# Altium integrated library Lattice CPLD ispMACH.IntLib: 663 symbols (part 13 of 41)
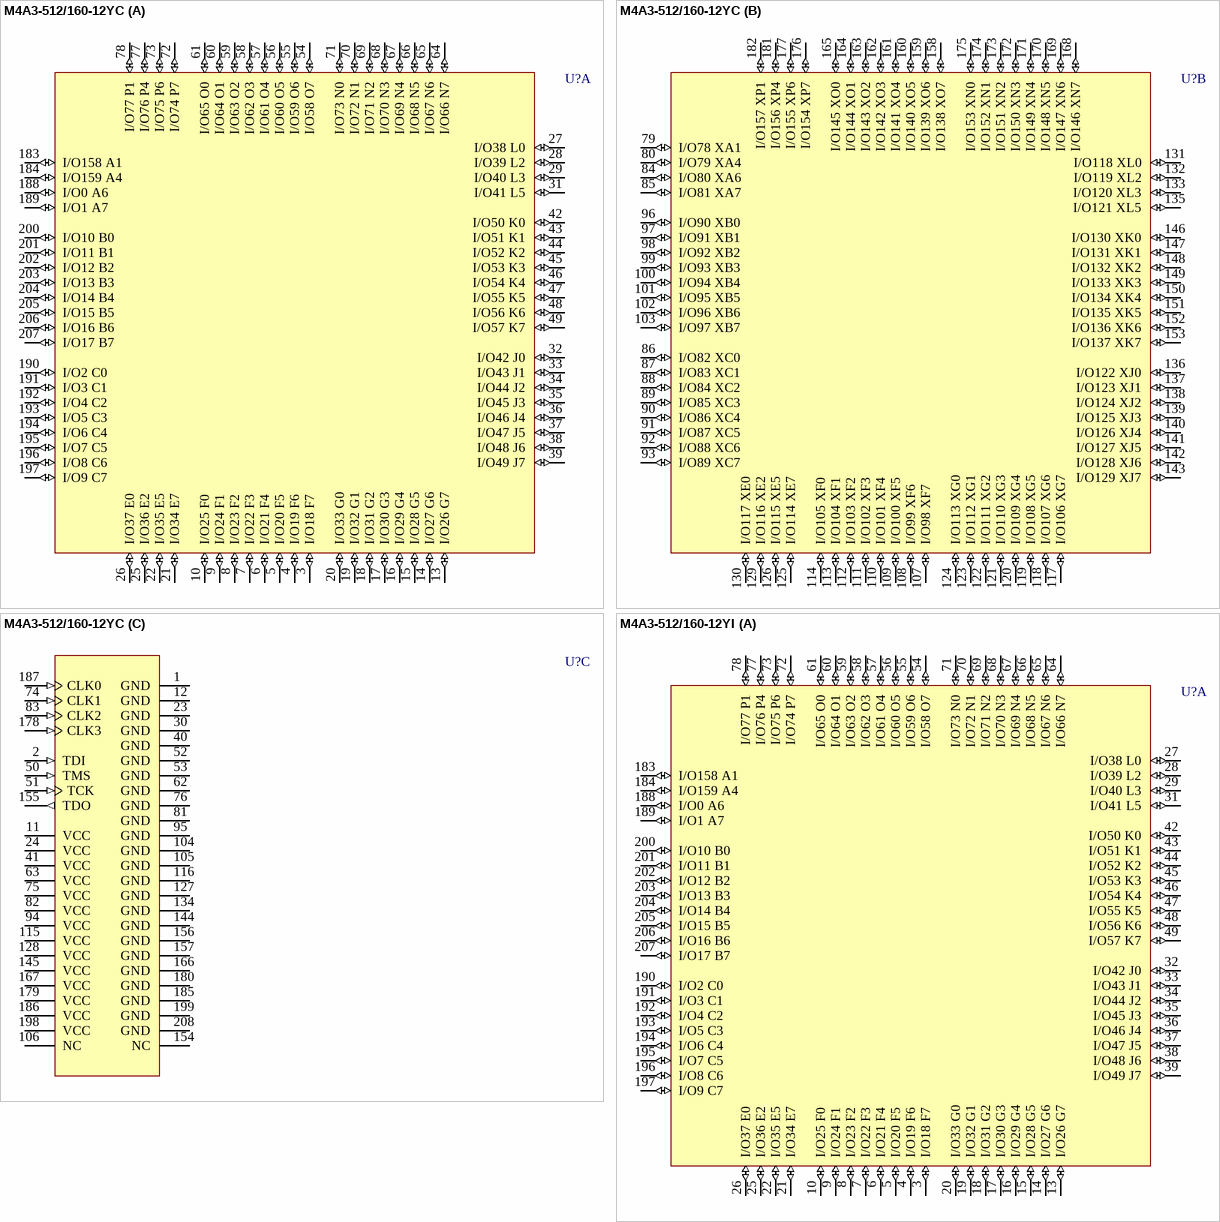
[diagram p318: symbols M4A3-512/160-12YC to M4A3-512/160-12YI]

## M4A3-512/160-12YC
designator U?
High-Performance EE CMOS In-System Programmable Logic
footprint PQFP208_N (Shrink QFP, 208-Leads, Body 28x28mm, Pitch 0.5mm, IPC Medium Density)
footprint PQFP208_L (Shrink QFP, 208-Leads, Body 28x28mm, Pitch 0.5mm, IPC High Density)
footprint PQFP208_M (Shrink QFP, 208-Leads, Body 28x28mm, Pitch 0.5mm, IPC Low Density)
3D model M4A3-PQFP208 (208-Pin Plastic Quad Flat Pack (PQFP208))
part A pins: 3 I/O18 F7 (io), 4 I/O19 F6 (io), 5 I/O20 F5 (io), 6 I/O21 F4 (io), 7 I/O22 F3 (io), 8 I/O23 F2 (io), 9 I/O24 F1 (io), 10 I/O25 F0 (io), 13 I/O26 G7 (io), 14 I/O27 G6 (io), 15 I/O28 G5 (io), 16 I/O29 G4 (io), 17 I/O30 G3 (io), 18 I/O31 G2 (io), 19 I/O32 G1 (io), 20 I/O33 G0 (io), 21 I/O34 E7 (io), 22 I/O35 E5 (io), 25 I/O36 E2 (io), 26 I/O37 E0 (io), 27 I/O38 L0 (io), 28 I/O39 L2 (io), 29 I/O40 L3 (io), 31 I/O41 L5 (io), 32 I/O42 J0 (io), 33 I/O43 J1 (io), 34 I/O44 J2 (io), 35 I/O45 J3 (io), 36 I/O46 J4 (io), 37 I/O47 J5 (io), 38 I/O48 J6 (io), 39 I/O49 J7 (io), 42 I/O50 K0 (io), 43 I/O51 K1 (io), 44 I/O52 K2 (io), 45 I/O53 K3 (io), 46 I/O54 K4 (io), 47 I/O55 K5 (io), 48 I/O56 K6 (io), 49 I/O57 K7 (io), 54 I/O58 O7 (io), 55 I/O59 O6 (io), 56 I/O60 O5 (io), 57 I/O61 O4 (io), 58 I/O62 O3 (io), 59 I/O63 O2 (io), 60 I/O64 O1 (io), 61 I/O65 O0 (io), 64 I/O66 N7 (io), 65 I/O67 N6 (io), 66 I/O68 N5 (io), 67 I/O69 N4 (io), 68 I/O70 N3 (io), 69 I/O71 N2 (io), 70 I/O72 N1 (io), 71 I/O73 N0 (io), 72 I/O74 P7 (io), 73 I/O75 P6 (io), 77 I/O76 P4 (io), 78 I/O77 P1 (io), 183 I/O158 A1 (io), 184 I/O159 A4 (io), 188 I/O0 A6 (io), 189 I/O1 A7 (io), 190 I/O2 C0 (io), 191 I/O3 C1 (io), 192 I/O4 C2 (io), 193 I/O5 C3 (io), 194 I/O6 C4 (io), 195 I/O7 C5 (io), 196 I/O8 C6 (io), 197 I/O9 C7 (io), 200 I/O10 B0 (io), 201 I/O11 B1 (io), 202 I/O12 B2 (io), 203 I/O13 B3 (io), 204 I/O14 B4 (io), 205 I/O15 B5 (io), 206 I/O16 B6 (io), 207 I/O17 B7 (io)
part B pins: 79 I/O78 XA1 (io), 80 I/O79 XA4 (io), 84 I/O80 XA6 (io), 85 I/O81 XA7 (io), 86 I/O82 XC0 (io), 87 I/O83 XC1 (io), 88 I/O84 XC2 (io), 89 I/O85 XC3 (io), 90 I/O86 XC4 (io), 91 I/O87 XC5 (io), 92 I/O88 XC6 (io), 93 I/O89 XC7 (io), 96 I/O90 XB0 (io), 97 I/O91 XB1 (io), 98 I/O92 XB2 (io), 99 I/O93 XB3 (io), 100 I/O94 XB4 (io), 101 I/O95 XB5 (io), 102 I/O96 XB6 (io), 103 I/O97 XB7 (io), 107 I/O98 XF7 (io), 108 I/O99 XF6 (io), 109 I/O100 XF5 (io), 110 I/O101 XF4 (io), 111 I/O102 XF3 (io), 112 I/O103 XF2 (io), 113 I/O104 XF1 (io), 114 I/O105 XF0 (io), 117 I/O106 XG7 (io), 118 I/O107 XG6 (io), 119 I/O108 XG5 (io), 120 I/O109 XG4 (io), 121 I/O110 XG3 (io), 122 I/O111 XG2 (io), 123 I/O112 XG1 (io), 124 I/O113 XG0 (io), 125 I/O114 XE7 (io), 126 I/O115 XE5 (io), 129 I/O116 XE2 (io), 130 I/O117 XE0 (io), 131 I/O118 XL0 (io), 132 I/O119 XL2 (io), 133 I/O120 XL3 (io), 135 I/O121 XL5 (io), 136 I/O122 XJ0 (io), 137 I/O123 XJ1 (io), 138 I/O124 XJ2 (io), 139 I/O125 XJ3 (io), 140 I/O126 XJ4 (io), 141 I/O127 XJ5 (io), 142 I/O128 XJ6 (io), 143 I/O129 XJ7 (io), 146 I/O130 XK0 (io), 147 I/O131 XK1 (io), 148 I/O132 XK2 (io), 149 I/O133 XK3 (io), 150 I/O134 XK4 (io), 151 I/O135 XK5 (io), 152 I/O136 XK6 (io), 153 I/O137 XK7 (io), 158 I/O138 XO7 (io), 159 I/O139 XO6 (io), 160 I/O140 XO5 (io), 161 I/O141 XO4 (io), 162 I/O142 XO3 (io), 163 I/O143 XO2 (io), 164 I/O144 XO1 (io), 165 I/O145 XO0 (io), 168 I/O146 XN7 (io), 169 I/O147 XN6 (io), 170 I/O148 XN5 (io), 171 I/O149 XN4 (io), 172 I/O150 XN3 (io), 173 I/O151 XN2 (io), 174 I/O152 XN1 (io), 175 I/O153 XN0 (io), 176 I/O154 XP7 (io), 177 I/O155 XP6 (io), 181 I/O156 XP4 (io), 182 I/O157 XP1 (io)
part C pins: 1 GND (power), 2 TDI (in), 11 VCC (power), 12 GND (power), 23 GND (power), 24 VCC (power), 30 GND (power), 40 GND (power), 41 VCC (power), 50 TMS (in), 51 TCK (in), 52 GND (power), 53 GND (power), 62 GND (power), 63 VCC (power), 74 CLK1 (in), 75 VCC (power), 76 GND (power), 81 GND (power), 82 VCC (power), 83 CLK2 (in), 94 VCC (power), 95 GND (power), 104 GND (power), 105 GND (power), 106 NC, 115 VCC (power), 116 GND (power), 127 GND (power), 128 VCC (power), 134 GND (power), 144 GND (power), 145 VCC (power), 154 NC, 155 TDO (out), 156 GND (power), 157 GND (power), 166 GND (power), 167 VCC (power), 178 CLK3 (in), 179 VCC (power), 180 GND (power), 185 GND (power), 186 VCC (power), 187 CLK0 (in), 198 VCC (power), 199 GND (power), 208 GND (power)

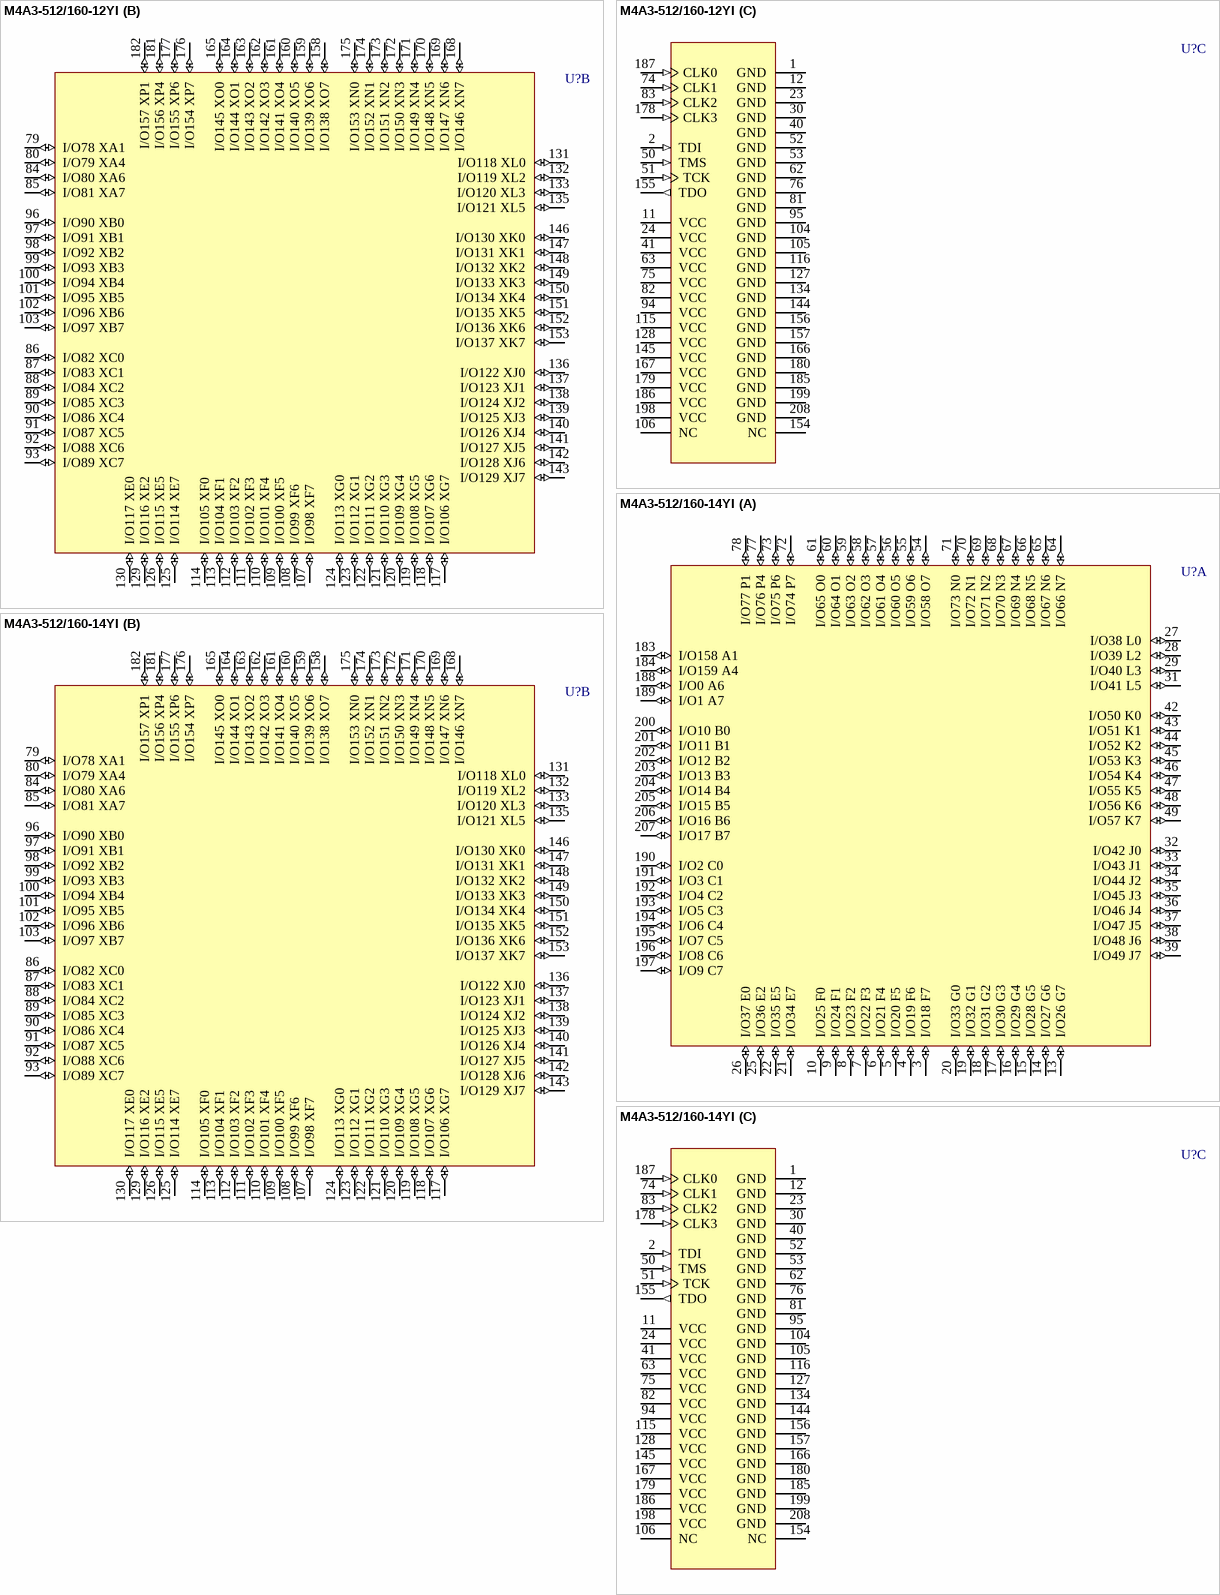
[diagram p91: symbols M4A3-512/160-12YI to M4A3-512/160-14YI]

## M4A3-512/160-12YI
designator U?
High-Performance EE CMOS In-System Programmable Logic
footprint PQFP208_N (Shrink QFP, 208-Leads, Body 28x28mm, Pitch 0.5mm, IPC Medium Density)
footprint PQFP208_L (Shrink QFP, 208-Leads, Body 28x28mm, Pitch 0.5mm, IPC High Density)
footprint PQFP208_M (Shrink QFP, 208-Leads, Body 28x28mm, Pitch 0.5mm, IPC Low Density)
3D model M4A3-PQFP208 (208-Pin Plastic Quad Flat Pack (PQFP208))
part A pins: 3 I/O18 F7 (io), 4 I/O19 F6 (io), 5 I/O20 F5 (io), 6 I/O21 F4 (io), 7 I/O22 F3 (io), 8 I/O23 F2 (io), 9 I/O24 F1 (io), 10 I/O25 F0 (io), 13 I/O26 G7 (io), 14 I/O27 G6 (io), 15 I/O28 G5 (io), 16 I/O29 G4 (io), 17 I/O30 G3 (io), 18 I/O31 G2 (io), 19 I/O32 G1 (io), 20 I/O33 G0 (io), 21 I/O34 E7 (io), 22 I/O35 E5 (io), 25 I/O36 E2 (io), 26 I/O37 E0 (io), 27 I/O38 L0 (io), 28 I/O39 L2 (io), 29 I/O40 L3 (io), 31 I/O41 L5 (io), 32 I/O42 J0 (io), 33 I/O43 J1 (io), 34 I/O44 J2 (io), 35 I/O45 J3 (io), 36 I/O46 J4 (io), 37 I/O47 J5 (io), 38 I/O48 J6 (io), 39 I/O49 J7 (io), 42 I/O50 K0 (io), 43 I/O51 K1 (io), 44 I/O52 K2 (io), 45 I/O53 K3 (io), 46 I/O54 K4 (io), 47 I/O55 K5 (io), 48 I/O56 K6 (io), 49 I/O57 K7 (io), 54 I/O58 O7 (io), 55 I/O59 O6 (io), 56 I/O60 O5 (io), 57 I/O61 O4 (io), 58 I/O62 O3 (io), 59 I/O63 O2 (io), 60 I/O64 O1 (io), 61 I/O65 O0 (io), 64 I/O66 N7 (io), 65 I/O67 N6 (io), 66 I/O68 N5 (io), 67 I/O69 N4 (io), 68 I/O70 N3 (io), 69 I/O71 N2 (io), 70 I/O72 N1 (io), 71 I/O73 N0 (io), 72 I/O74 P7 (io), 73 I/O75 P6 (io), 77 I/O76 P4 (io), 78 I/O77 P1 (io), 183 I/O158 A1 (io), 184 I/O159 A4 (io), 188 I/O0 A6 (io), 189 I/O1 A7 (io), 190 I/O2 C0 (io), 191 I/O3 C1 (io), 192 I/O4 C2 (io), 193 I/O5 C3 (io), 194 I/O6 C4 (io), 195 I/O7 C5 (io), 196 I/O8 C6 (io), 197 I/O9 C7 (io), 200 I/O10 B0 (io), 201 I/O11 B1 (io), 202 I/O12 B2 (io), 203 I/O13 B3 (io), 204 I/O14 B4 (io), 205 I/O15 B5 (io), 206 I/O16 B6 (io), 207 I/O17 B7 (io)
part B pins: 79 I/O78 XA1 (io), 80 I/O79 XA4 (io), 84 I/O80 XA6 (io), 85 I/O81 XA7 (io), 86 I/O82 XC0 (io), 87 I/O83 XC1 (io), 88 I/O84 XC2 (io), 89 I/O85 XC3 (io), 90 I/O86 XC4 (io), 91 I/O87 XC5 (io), 92 I/O88 XC6 (io), 93 I/O89 XC7 (io), 96 I/O90 XB0 (io), 97 I/O91 XB1 (io), 98 I/O92 XB2 (io), 99 I/O93 XB3 (io), 100 I/O94 XB4 (io), 101 I/O95 XB5 (io), 102 I/O96 XB6 (io), 103 I/O97 XB7 (io), 107 I/O98 XF7 (io), 108 I/O99 XF6 (io), 109 I/O100 XF5 (io), 110 I/O101 XF4 (io), 111 I/O102 XF3 (io), 112 I/O103 XF2 (io), 113 I/O104 XF1 (io), 114 I/O105 XF0 (io), 117 I/O106 XG7 (io), 118 I/O107 XG6 (io), 119 I/O108 XG5 (io), 120 I/O109 XG4 (io), 121 I/O110 XG3 (io), 122 I/O111 XG2 (io), 123 I/O112 XG1 (io), 124 I/O113 XG0 (io), 125 I/O114 XE7 (io), 126 I/O115 XE5 (io), 129 I/O116 XE2 (io), 130 I/O117 XE0 (io), 131 I/O118 XL0 (io), 132 I/O119 XL2 (io), 133 I/O120 XL3 (io), 135 I/O121 XL5 (io), 136 I/O122 XJ0 (io), 137 I/O123 XJ1 (io), 138 I/O124 XJ2 (io), 139 I/O125 XJ3 (io), 140 I/O126 XJ4 (io), 141 I/O127 XJ5 (io), 142 I/O128 XJ6 (io), 143 I/O129 XJ7 (io), 146 I/O130 XK0 (io), 147 I/O131 XK1 (io), 148 I/O132 XK2 (io), 149 I/O133 XK3 (io), 150 I/O134 XK4 (io), 151 I/O135 XK5 (io), 152 I/O136 XK6 (io), 153 I/O137 XK7 (io), 158 I/O138 XO7 (io), 159 I/O139 XO6 (io), 160 I/O140 XO5 (io), 161 I/O141 XO4 (io), 162 I/O142 XO3 (io), 163 I/O143 XO2 (io), 164 I/O144 XO1 (io), 165 I/O145 XO0 (io), 168 I/O146 XN7 (io), 169 I/O147 XN6 (io), 170 I/O148 XN5 (io), 171 I/O149 XN4 (io), 172 I/O150 XN3 (io), 173 I/O151 XN2 (io), 174 I/O152 XN1 (io), 175 I/O153 XN0 (io), 176 I/O154 XP7 (io), 177 I/O155 XP6 (io), 181 I/O156 XP4 (io), 182 I/O157 XP1 (io)
part C pins: 1 GND (power), 2 TDI (in), 11 VCC (power), 12 GND (power), 23 GND (power), 24 VCC (power), 30 GND (power), 40 GND (power), 41 VCC (power), 50 TMS (in), 51 TCK (in), 52 GND (power), 53 GND (power), 62 GND (power), 63 VCC (power), 74 CLK1 (in), 75 VCC (power), 76 GND (power), 81 GND (power), 82 VCC (power), 83 CLK2 (in), 94 VCC (power), 95 GND (power), 104 GND (power), 105 GND (power), 106 NC, 115 VCC (power), 116 GND (power), 127 GND (power), 128 VCC (power), 134 GND (power), 144 GND (power), 145 VCC (power), 154 NC, 155 TDO (out), 156 GND (power), 157 GND (power), 166 GND (power), 167 VCC (power), 178 CLK3 (in), 179 VCC (power), 180 GND (power), 185 GND (power), 186 VCC (power), 187 CLK0 (in), 198 VCC (power), 199 GND (power), 208 GND (power)

## M4A3-512/160-14YI
designator U?
High-Performance EE CMOS In-System Programmable Logic
footprint PQFP208_N (Shrink QFP, 208-Leads, Body 28x28mm, Pitch 0.5mm, IPC Medium Density)
footprint PQFP208_L (Shrink QFP, 208-Leads, Body 28x28mm, Pitch 0.5mm, IPC High Density)
footprint PQFP208_M (Shrink QFP, 208-Leads, Body 28x28mm, Pitch 0.5mm, IPC Low Density)
3D model M4A3-PQFP208 (208-Pin Plastic Quad Flat Pack (PQFP208))
part A pins: 3 I/O18 F7 (io), 4 I/O19 F6 (io), 5 I/O20 F5 (io), 6 I/O21 F4 (io), 7 I/O22 F3 (io), 8 I/O23 F2 (io), 9 I/O24 F1 (io), 10 I/O25 F0 (io), 13 I/O26 G7 (io), 14 I/O27 G6 (io), 15 I/O28 G5 (io), 16 I/O29 G4 (io), 17 I/O30 G3 (io), 18 I/O31 G2 (io), 19 I/O32 G1 (io), 20 I/O33 G0 (io), 21 I/O34 E7 (io), 22 I/O35 E5 (io), 25 I/O36 E2 (io), 26 I/O37 E0 (io), 27 I/O38 L0 (io), 28 I/O39 L2 (io), 29 I/O40 L3 (io), 31 I/O41 L5 (io), 32 I/O42 J0 (io), 33 I/O43 J1 (io), 34 I/O44 J2 (io), 35 I/O45 J3 (io), 36 I/O46 J4 (io), 37 I/O47 J5 (io), 38 I/O48 J6 (io), 39 I/O49 J7 (io), 42 I/O50 K0 (io), 43 I/O51 K1 (io), 44 I/O52 K2 (io), 45 I/O53 K3 (io), 46 I/O54 K4 (io), 47 I/O55 K5 (io), 48 I/O56 K6 (io), 49 I/O57 K7 (io), 54 I/O58 O7 (io), 55 I/O59 O6 (io), 56 I/O60 O5 (io), 57 I/O61 O4 (io), 58 I/O62 O3 (io), 59 I/O63 O2 (io), 60 I/O64 O1 (io), 61 I/O65 O0 (io), 64 I/O66 N7 (io), 65 I/O67 N6 (io), 66 I/O68 N5 (io), 67 I/O69 N4 (io), 68 I/O70 N3 (io), 69 I/O71 N2 (io), 70 I/O72 N1 (io), 71 I/O73 N0 (io), 72 I/O74 P7 (io), 73 I/O75 P6 (io), 77 I/O76 P4 (io), 78 I/O77 P1 (io), 183 I/O158 A1 (io), 184 I/O159 A4 (io), 188 I/O0 A6 (io), 189 I/O1 A7 (io), 190 I/O2 C0 (io), 191 I/O3 C1 (io), 192 I/O4 C2 (io), 193 I/O5 C3 (io), 194 I/O6 C4 (io), 195 I/O7 C5 (io), 196 I/O8 C6 (io), 197 I/O9 C7 (io), 200 I/O10 B0 (io), 201 I/O11 B1 (io), 202 I/O12 B2 (io), 203 I/O13 B3 (io), 204 I/O14 B4 (io), 205 I/O15 B5 (io), 206 I/O16 B6 (io), 207 I/O17 B7 (io)
part B pins: 79 I/O78 XA1 (io), 80 I/O79 XA4 (io), 84 I/O80 XA6 (io), 85 I/O81 XA7 (io), 86 I/O82 XC0 (io), 87 I/O83 XC1 (io), 88 I/O84 XC2 (io), 89 I/O85 XC3 (io), 90 I/O86 XC4 (io), 91 I/O87 XC5 (io), 92 I/O88 XC6 (io), 93 I/O89 XC7 (io), 96 I/O90 XB0 (io), 97 I/O91 XB1 (io), 98 I/O92 XB2 (io), 99 I/O93 XB3 (io), 100 I/O94 XB4 (io), 101 I/O95 XB5 (io), 102 I/O96 XB6 (io), 103 I/O97 XB7 (io), 107 I/O98 XF7 (io), 108 I/O99 XF6 (io), 109 I/O100 XF5 (io), 110 I/O101 XF4 (io), 111 I/O102 XF3 (io), 112 I/O103 XF2 (io), 113 I/O104 XF1 (io), 114 I/O105 XF0 (io), 117 I/O106 XG7 (io), 118 I/O107 XG6 (io), 119 I/O108 XG5 (io), 120 I/O109 XG4 (io), 121 I/O110 XG3 (io), 122 I/O111 XG2 (io), 123 I/O112 XG1 (io), 124 I/O113 XG0 (io), 125 I/O114 XE7 (io), 126 I/O115 XE5 (io), 129 I/O116 XE2 (io), 130 I/O117 XE0 (io), 131 I/O118 XL0 (io), 132 I/O119 XL2 (io), 133 I/O120 XL3 (io), 135 I/O121 XL5 (io), 136 I/O122 XJ0 (io), 137 I/O123 XJ1 (io), 138 I/O124 XJ2 (io), 139 I/O125 XJ3 (io), 140 I/O126 XJ4 (io), 141 I/O127 XJ5 (io), 142 I/O128 XJ6 (io), 143 I/O129 XJ7 (io), 146 I/O130 XK0 (io), 147 I/O131 XK1 (io), 148 I/O132 XK2 (io), 149 I/O133 XK3 (io), 150 I/O134 XK4 (io), 151 I/O135 XK5 (io), 152 I/O136 XK6 (io), 153 I/O137 XK7 (io), 158 I/O138 XO7 (io), 159 I/O139 XO6 (io), 160 I/O140 XO5 (io), 161 I/O141 XO4 (io), 162 I/O142 XO3 (io), 163 I/O143 XO2 (io), 164 I/O144 XO1 (io), 165 I/O145 XO0 (io), 168 I/O146 XN7 (io), 169 I/O147 XN6 (io), 170 I/O148 XN5 (io), 171 I/O149 XN4 (io), 172 I/O150 XN3 (io), 173 I/O151 XN2 (io), 174 I/O152 XN1 (io), 175 I/O153 XN0 (io), 176 I/O154 XP7 (io), 177 I/O155 XP6 (io), 181 I/O156 XP4 (io), 182 I/O157 XP1 (io)
part C pins: 1 GND (power), 2 TDI (in), 11 VCC (power), 12 GND (power), 23 GND (power), 24 VCC (power), 30 GND (power), 40 GND (power), 41 VCC (power), 50 TMS (in), 51 TCK (in), 52 GND (power), 53 GND (power), 62 GND (power), 63 VCC (power), 74 CLK1 (in), 75 VCC (power), 76 GND (power), 81 GND (power), 82 VCC (power), 83 CLK2 (in), 94 VCC (power), 95 GND (power), 104 GND (power), 105 GND (power), 106 NC, 115 VCC (power), 116 GND (power), 127 GND (power), 128 VCC (power), 134 GND (power), 144 GND (power), 145 VCC (power), 154 NC, 155 TDO (out), 156 GND (power), 157 GND (power), 166 GND (power), 167 VCC (power), 178 CLK3 (in), 179 VCC (power), 180 GND (power), 185 GND (power), 186 VCC (power), 187 CLK0 (in), 198 VCC (power), 199 GND (power), 208 GND (power)

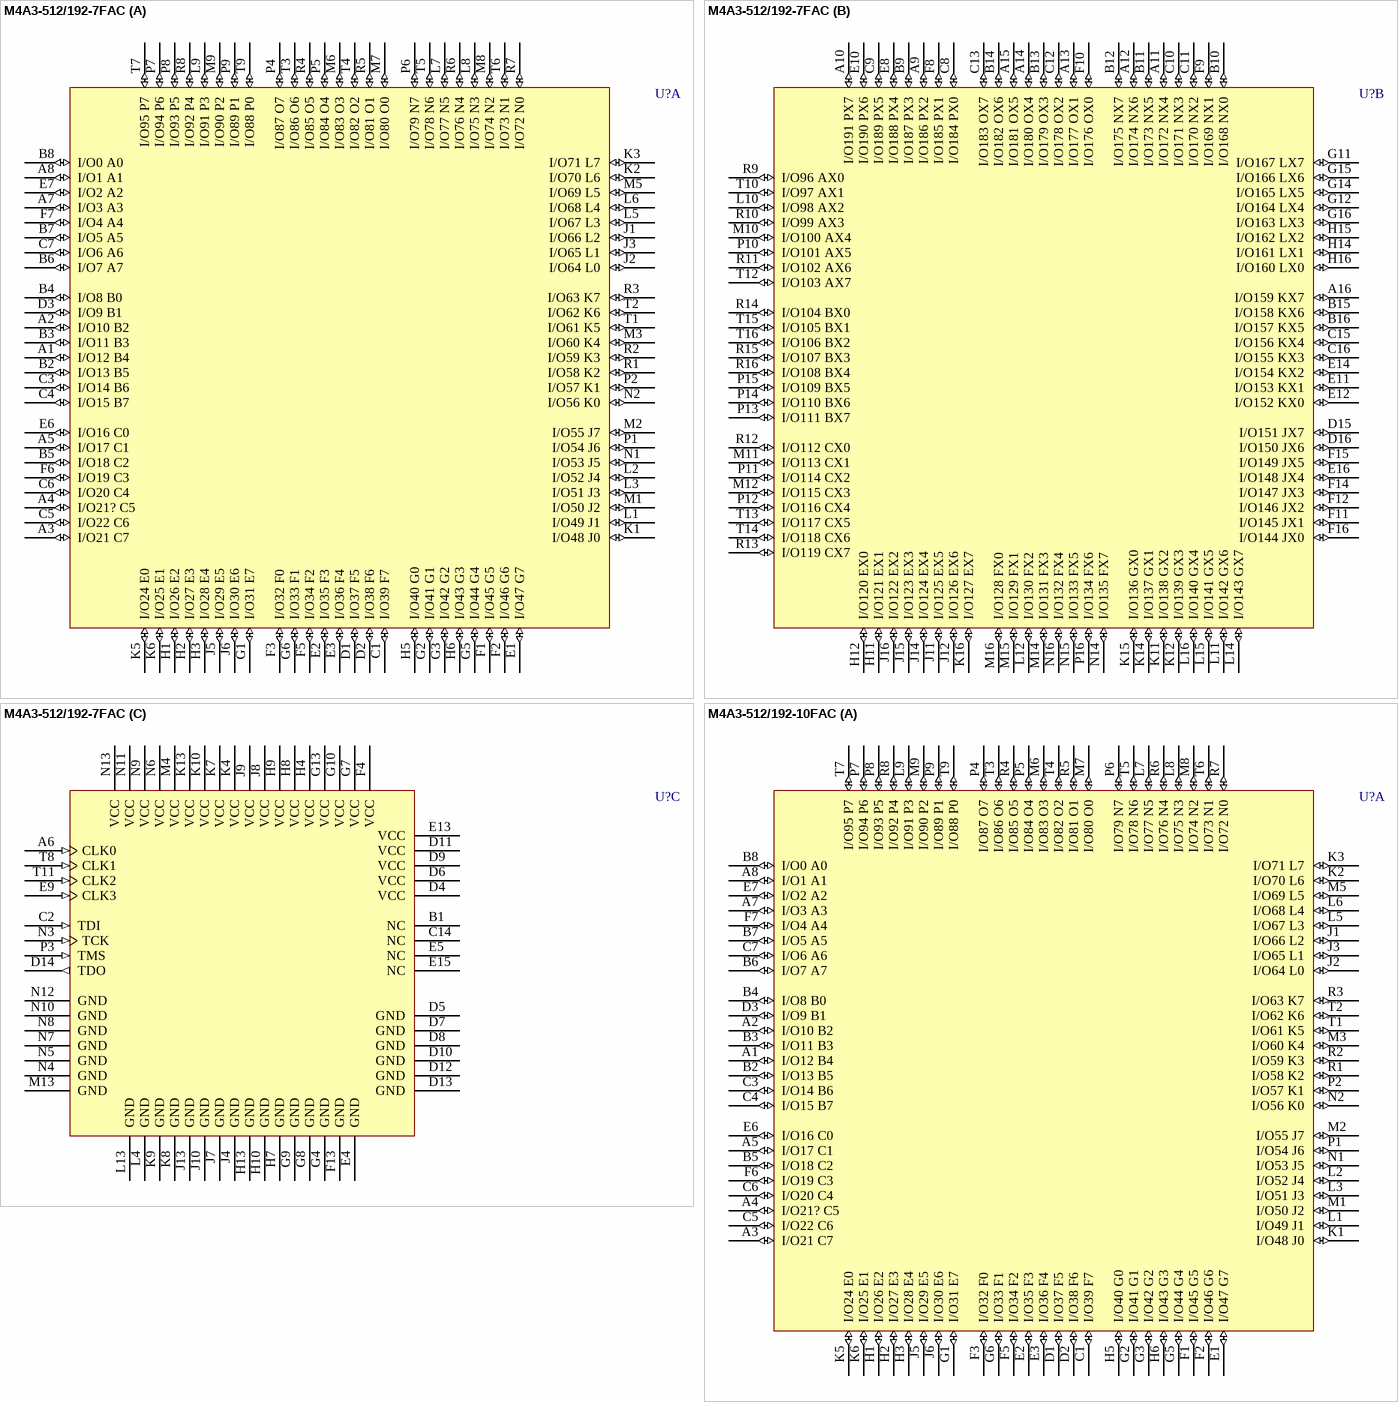
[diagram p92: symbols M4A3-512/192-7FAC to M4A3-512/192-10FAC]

## M4A3-512/192-7FAC
designator U?
High-Performance EE CMOS In-System Programmable Logic
footprint fpBGA256 (BGA, 256-Leads, Body 17x17mm, Pitch 1mm)
3D model M4A3-fpBGA256 (256-Ball Fine Pitch Ball Grid Array (fpBGA256))
part A pins: A1 I/O12 B4 (io), A2 I/O10 B2 (io), A3 I/O21 C7 (io), A4 I/O21? C5 (io), A5 I/O17 C1 (io), A7 I/O3 A3 (io), A8 I/O1 A1 (io), B2 I/O13 B5 (io), B3 I/O11 B3 (io), B4 I/O8 B0 (io), B5 I/O18 C2 (io), B6 I/O7 A7 (io), B7 I/O5 A5 (io), B8 I/O0 A0 (io), C1 I/O39 F7 (io), C3 I/O14 B6 (io), C4 I/O15 B7 (io), C5 I/O22 C6 (io), C6 I/O20 C4 (io), C7 I/O6 A6 (io), D1 I/O37 F5 (io), D2 I/O38 F6 (io), D3 I/O9 B1 (io), E1 I/O47 G7 (io), E2 I/O35 F3 (io), E3 I/O36 F4 (io), E6 I/O16 C0 (io), E7 I/O2 A2 (io), F1 I/O45 G5 (io), F2 I/O46 G6 (io), F3 I/O32 F0 (io), F5 I/O34 F2 (io), F6 I/O19 C3 (io), F7 I/O4 A4 (io), G1 I/O31 E7 (io), G2 I/O41 G1 (io), G3 I/O42 G2 (io), G5 I/O44 G4 (io), G6 I/O33 F1 (io), H1 I/O26 E2 (io), H2 I/O27 E3 (io), H3 I/O28 E4 (io), H5 I/O40 G0 (io), H6 I/O43 G3 (io), J1 I/O66 L2 (io), J2 I/O64 L0 (io), J3 I/O65 L1 (io), J5 I/O29 E5 (io), J6 I/O30 E6 (io), K1 I/O48 J0 (io), K2 I/O70 L6 (io), K3 I/O71 L7 (io), K5 I/O24 E0 (io), K6 I/O25 E1 (io), L1 I/O49 J1 (io), L2 I/O52 J4 (io), L3 I/O51 J3 (io), L5 I/O67 L3 (io), L6 I/O68 L4 (io), L7 I/O77 N5 (io), L8 I/O75 N3 (io), L9 I/O91 P3 (io), M1 I/O50 J2 (io), M2 I/O55 J7 (io), M3 I/O60 K4 (io), M5 I/O69 L5 (io), M6 I/O83 O3 (io), M7 I/O80 O0 (io), M8 I/O74 N2 (io), M9 I/O90 P2 (io), N1 I/O53 J5 (io), N2 I/O56 K0 (io), P1 I/O54 J6 (io), P2 I/O57 K1 (io), P4 I/O87 O7 (io), P5 I/O84 O4 (io), P6 I/O79 N7 (io), P7 I/O94 P6 (io), P8 I/O93 P5 (io), P9 I/O89 P1 (io), R1 I/O58 K2 (io), R2 I/O59 K3 (io), R3 I/O63 K7 (io), R4 I/O85 O5 (io), R5 I/O81 O1 (io), R6 I/O76 N4 (io), R7 I/O72 N0 (io), R8 I/O92 P4 (io), T1 I/O61 K5 (io), T2 I/O62 K6 (io), T3 I/O86 O6 (io), T4 I/O82 O2 (io), T5 I/O78 N6 (io), T6 I/O73 N1 (io), T7 I/O95 P7 (io), T9 I/O88 P0 (io)
part B pins: A9 I/O186 PX2 (io), A10 I/O191 PX7 (io), A11 I/O172 NX4 (io), A12 I/O174 NX6 (io), A13 I/O177 OX1 (io), A14 I/O180 OX4 (io), A15 I/O181 OX5 (io), A16 I/O159 KX7 (io), B9 I/O187 PX3 (io), B10 I/O168 NX0 (io), B11 I/O173 NX5 (io), B12 I/O175 NX7 (io), B13 I/O179 OX3 (io), B14 I/O182 OX6 (io), B15 I/O158 KX6 (io), B16 I/O157 KX5 (io), C8 I/O184 PX0 (io), C9 I/O189 PX5 (io), C10 I/O171 NX3 (io), C11 I/O170 NX2 (io), C12 I/O178 OX2 (io), C13 I/O183 OX7 (io), C15 I/O156 KX4 (io), C16 I/O155 KX3 (io), D15 I/O151 JX7 (io), D16 I/O150 JX6 (io), E8 I/O188 PX4 (io), E10 I/O190 PX6 (io), E11 I/O153 KX1 (io), E12 I/O152 KX0 (io), E14 I/O154 KX2 (io), E16 I/O148 JX4 (io), F8 I/O185 PX1 (io), F9 I/O169 NX1 (io), F10 I/O176 OX0 (io), F11 I/O145 JX1 (io), F12 I/O146 JX2 (io), F14 I/O147 JX3 (io), F15 I/O149 JX5 (io), F16 I/O144 JX0 (io), G11 I/O167 LX7 (io), G12 I/O164 LX4 (io), G14 I/O165 LX5 (io), G15 I/O166 LX6 (io), G16 I/O163 LX3 (io), H11 I/O121 EX1 (io), H12 I/O120 EX0 (io), H14 I/O161 LX1 (io), H15 I/O162 LX2 (io), H16 I/O160 LX0 (io), J11 I/O125 EX5 (io), J12 I/O126 EX6 (io), J14 I/O124 EX4 (io), J15 I/O123 EX3 (io), J16 I/O122 EX2 (io), K11 I/O138 GX2 (io), K12 I/O139 GX3 (io), K14 I/O137 GX1 (io), K15 I/O136 GX0 (io), K16 I/O127 EX7 (io), L10 I/O98 AX2 (io), L11 I/O142 GX6 (io), L12 I/O130 FX2 (io), L14 I/O143 GX7 (io), L15 I/O141 GX5 (io), L16 I/O140 GX4 (io), M10 I/O100 AX4 (io), M11 I/O113 CX1 (io), M12 I/O115 CX3 (io), M14 I/O131 FX3 (io), M15 I/O129 FX1 (io), M16 I/O128 FX0 (io), N14 I/O135 FX7 (io), N15 I/O133 FX5 (io), N16 I/O132 FX4 (io), P10 I/O101 AX5 (io), P11 I/O114 CX2 (io), P12 I/O116 CX4 (io), P13 I/O111 BX7 (io), P14 I/O110 BX6 (io), P15 I/O109 BX5 (io), P16 I/O134 FX6 (io), R9 I/O96 AX0 (io), R10 I/O99 AX3 (io), R11 I/O102 AX6 (io), R12 I/O112 CX0 (io), R13 I/O119 CX7 (io), R14 I/O104 BX0 (io), R15 I/O107 BX3 (io), R16 I/O108 BX4 (io), T10 I/O97 AX1 (io), T12 I/O103 AX7 (io), T13 I/O117 CX5 (io), T14 I/O118 CX6 (io), T15 I/O105 BX1 (io), T16 I/O106 BX2 (io)
part C pins: A6 CLK0 (in), B1 NC, C2 TDI (in), C14 NC, D4 VCC (power), D5 GND (power), D6 VCC (power), D7 GND (power), D8 GND (power), D9 VCC (power), D10 GND (power), D11 VCC (power), D12 GND (power), D13 GND (power), D14 TDO (out), E4 GND (power), E5 NC, E9 CLK3 (in), E13 VCC (power), E15 NC, F4 VCC (power), F13 GND (power), G4 GND (power), G7 VCC (power), G8 GND (power), G9 GND (power), G10 VCC (power), G13 VCC (power), H4 VCC (power), H7 GND (power), H8 VCC (power), H9 VCC (power), H10 GND (power), H13 GND (power), J4 GND (power), J7 GND (power), J8 VCC (power), J9 VCC (power), J10 GND (power), J13 GND (power), K4 VCC (power), K7 VCC (power), K8 GND (power), K9 GND (power), K10 VCC (power), K13 VCC (power), L4 GND (power), L13 GND (power), M4 VCC (power), M13 GND (power), N3 TCK (in), N4 GND (power), N5 GND (power), N6 VCC (power), N7 GND (power), N8 GND (power), N9 VCC (power), N10 GND (power), N11 VCC (power), N12 GND (power), N13 VCC (power), P3 TMS (in), T8 CLK1 (in), T11 CLK2 (in)

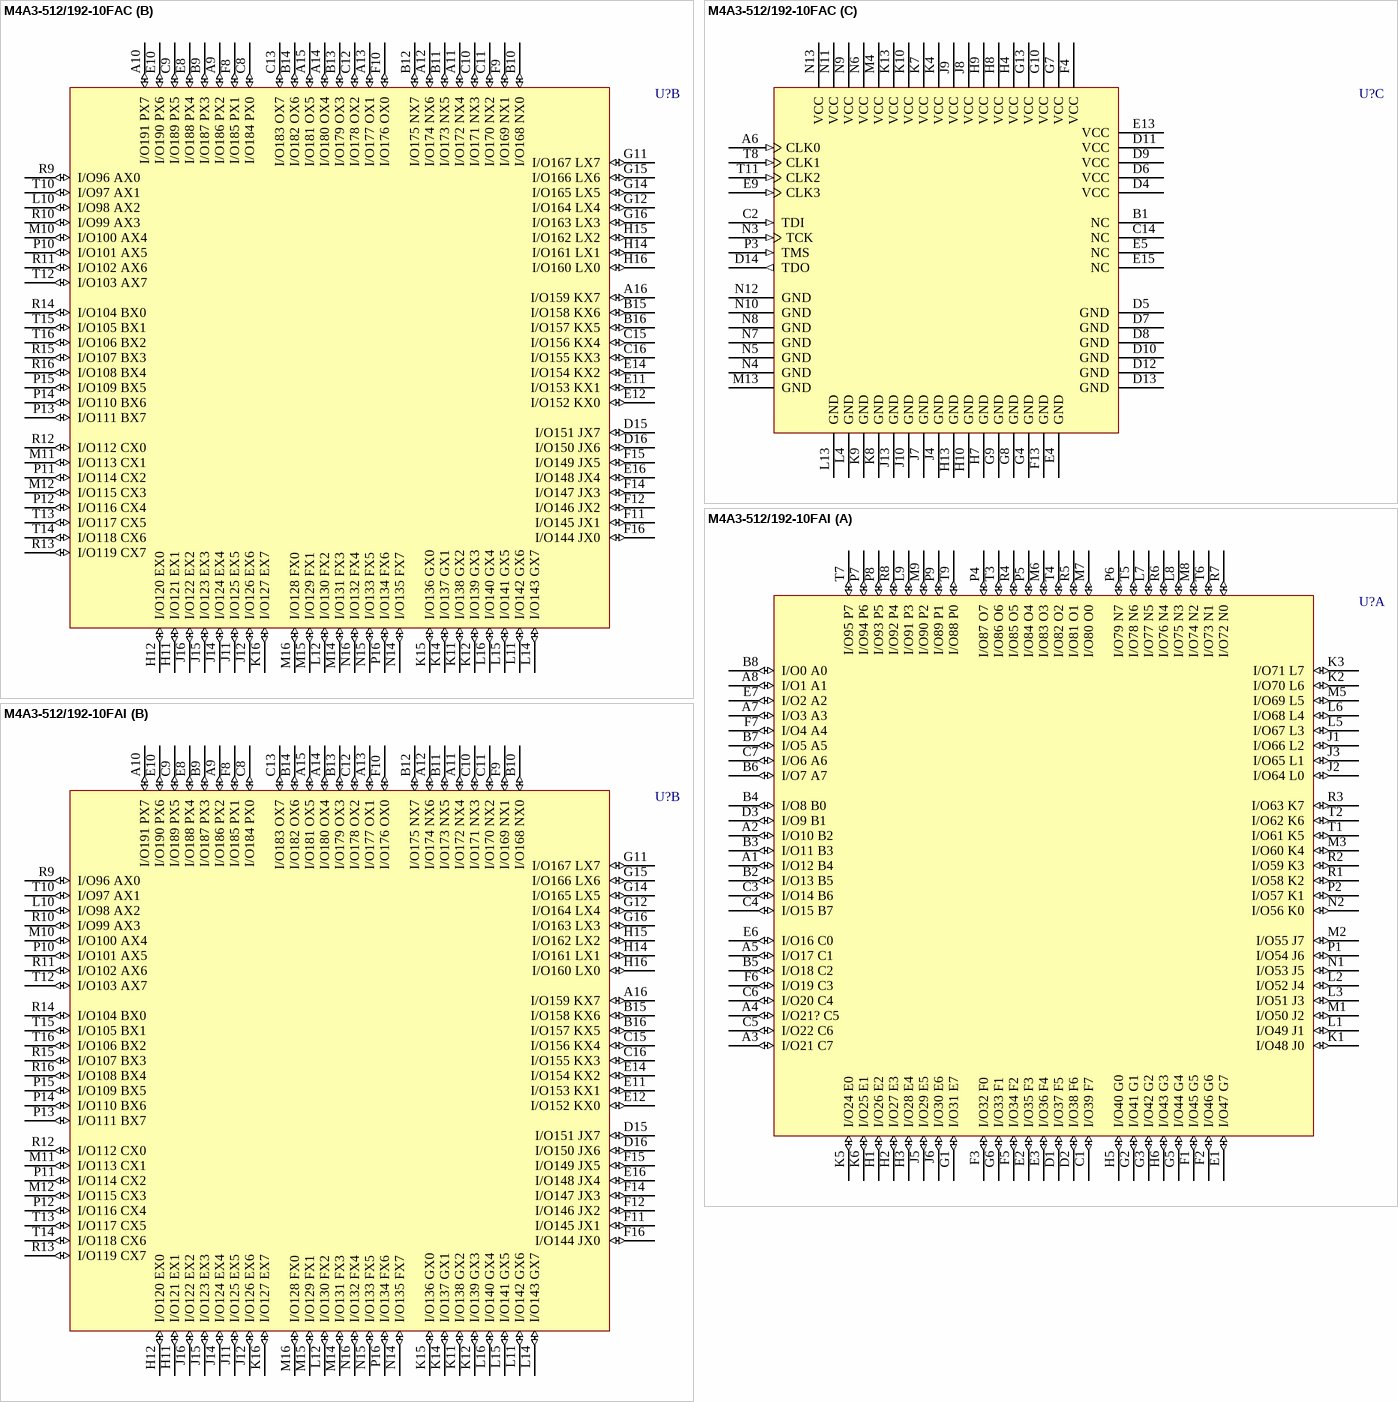
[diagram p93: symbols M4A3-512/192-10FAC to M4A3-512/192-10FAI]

## M4A3-512/192-10FAC
designator U?
High-Performance EE CMOS In-System Programmable Logic
footprint fpBGA256 (BGA, 256-Leads, Body 17x17mm, Pitch 1mm)
3D model M4A3-fpBGA256 (256-Ball Fine Pitch Ball Grid Array (fpBGA256))
part A pins: A1 I/O12 B4 (io), A2 I/O10 B2 (io), A3 I/O21 C7 (io), A4 I/O21? C5 (io), A5 I/O17 C1 (io), A7 I/O3 A3 (io), A8 I/O1 A1 (io), B2 I/O13 B5 (io), B3 I/O11 B3 (io), B4 I/O8 B0 (io), B5 I/O18 C2 (io), B6 I/O7 A7 (io), B7 I/O5 A5 (io), B8 I/O0 A0 (io), C1 I/O39 F7 (io), C3 I/O14 B6 (io), C4 I/O15 B7 (io), C5 I/O22 C6 (io), C6 I/O20 C4 (io), C7 I/O6 A6 (io), D1 I/O37 F5 (io), D2 I/O38 F6 (io), D3 I/O9 B1 (io), E1 I/O47 G7 (io), E2 I/O35 F3 (io), E3 I/O36 F4 (io), E6 I/O16 C0 (io), E7 I/O2 A2 (io), F1 I/O45 G5 (io), F2 I/O46 G6 (io), F3 I/O32 F0 (io), F5 I/O34 F2 (io), F6 I/O19 C3 (io), F7 I/O4 A4 (io), G1 I/O31 E7 (io), G2 I/O41 G1 (io), G3 I/O42 G2 (io), G5 I/O44 G4 (io), G6 I/O33 F1 (io), H1 I/O26 E2 (io), H2 I/O27 E3 (io), H3 I/O28 E4 (io), H5 I/O40 G0 (io), H6 I/O43 G3 (io), J1 I/O66 L2 (io), J2 I/O64 L0 (io), J3 I/O65 L1 (io), J5 I/O29 E5 (io), J6 I/O30 E6 (io), K1 I/O48 J0 (io), K2 I/O70 L6 (io), K3 I/O71 L7 (io), K5 I/O24 E0 (io), K6 I/O25 E1 (io), L1 I/O49 J1 (io), L2 I/O52 J4 (io), L3 I/O51 J3 (io), L5 I/O67 L3 (io), L6 I/O68 L4 (io), L7 I/O77 N5 (io), L8 I/O75 N3 (io), L9 I/O91 P3 (io), M1 I/O50 J2 (io), M2 I/O55 J7 (io), M3 I/O60 K4 (io), M5 I/O69 L5 (io), M6 I/O83 O3 (io), M7 I/O80 O0 (io), M8 I/O74 N2 (io), M9 I/O90 P2 (io), N1 I/O53 J5 (io), N2 I/O56 K0 (io), P1 I/O54 J6 (io), P2 I/O57 K1 (io), P4 I/O87 O7 (io), P5 I/O84 O4 (io), P6 I/O79 N7 (io), P7 I/O94 P6 (io), P8 I/O93 P5 (io), P9 I/O89 P1 (io), R1 I/O58 K2 (io), R2 I/O59 K3 (io), R3 I/O63 K7 (io), R4 I/O85 O5 (io), R5 I/O81 O1 (io), R6 I/O76 N4 (io), R7 I/O72 N0 (io), R8 I/O92 P4 (io), T1 I/O61 K5 (io), T2 I/O62 K6 (io), T3 I/O86 O6 (io), T4 I/O82 O2 (io), T5 I/O78 N6 (io), T6 I/O73 N1 (io), T7 I/O95 P7 (io), T9 I/O88 P0 (io)
part B pins: A9 I/O186 PX2 (io), A10 I/O191 PX7 (io), A11 I/O172 NX4 (io), A12 I/O174 NX6 (io), A13 I/O177 OX1 (io), A14 I/O180 OX4 (io), A15 I/O181 OX5 (io), A16 I/O159 KX7 (io), B9 I/O187 PX3 (io), B10 I/O168 NX0 (io), B11 I/O173 NX5 (io), B12 I/O175 NX7 (io), B13 I/O179 OX3 (io), B14 I/O182 OX6 (io), B15 I/O158 KX6 (io), B16 I/O157 KX5 (io), C8 I/O184 PX0 (io), C9 I/O189 PX5 (io), C10 I/O171 NX3 (io), C11 I/O170 NX2 (io), C12 I/O178 OX2 (io), C13 I/O183 OX7 (io), C15 I/O156 KX4 (io), C16 I/O155 KX3 (io), D15 I/O151 JX7 (io), D16 I/O150 JX6 (io), E8 I/O188 PX4 (io), E10 I/O190 PX6 (io), E11 I/O153 KX1 (io), E12 I/O152 KX0 (io), E14 I/O154 KX2 (io), E16 I/O148 JX4 (io), F8 I/O185 PX1 (io), F9 I/O169 NX1 (io), F10 I/O176 OX0 (io), F11 I/O145 JX1 (io), F12 I/O146 JX2 (io), F14 I/O147 JX3 (io), F15 I/O149 JX5 (io), F16 I/O144 JX0 (io), G11 I/O167 LX7 (io), G12 I/O164 LX4 (io), G14 I/O165 LX5 (io), G15 I/O166 LX6 (io), G16 I/O163 LX3 (io), H11 I/O121 EX1 (io), H12 I/O120 EX0 (io), H14 I/O161 LX1 (io), H15 I/O162 LX2 (io), H16 I/O160 LX0 (io), J11 I/O125 EX5 (io), J12 I/O126 EX6 (io), J14 I/O124 EX4 (io), J15 I/O123 EX3 (io), J16 I/O122 EX2 (io), K11 I/O138 GX2 (io), K12 I/O139 GX3 (io), K14 I/O137 GX1 (io), K15 I/O136 GX0 (io), K16 I/O127 EX7 (io), L10 I/O98 AX2 (io), L11 I/O142 GX6 (io), L12 I/O130 FX2 (io), L14 I/O143 GX7 (io), L15 I/O141 GX5 (io), L16 I/O140 GX4 (io), M10 I/O100 AX4 (io), M11 I/O113 CX1 (io), M12 I/O115 CX3 (io), M14 I/O131 FX3 (io), M15 I/O129 FX1 (io), M16 I/O128 FX0 (io), N14 I/O135 FX7 (io), N15 I/O133 FX5 (io), N16 I/O132 FX4 (io), P10 I/O101 AX5 (io), P11 I/O114 CX2 (io), P12 I/O116 CX4 (io), P13 I/O111 BX7 (io), P14 I/O110 BX6 (io), P15 I/O109 BX5 (io), P16 I/O134 FX6 (io), R9 I/O96 AX0 (io), R10 I/O99 AX3 (io), R11 I/O102 AX6 (io), R12 I/O112 CX0 (io), R13 I/O119 CX7 (io), R14 I/O104 BX0 (io), R15 I/O107 BX3 (io), R16 I/O108 BX4 (io), T10 I/O97 AX1 (io), T12 I/O103 AX7 (io), T13 I/O117 CX5 (io), T14 I/O118 CX6 (io), T15 I/O105 BX1 (io), T16 I/O106 BX2 (io)
part C pins: A6 CLK0 (in), B1 NC, C2 TDI (in), C14 NC, D4 VCC (power), D5 GND (power), D6 VCC (power), D7 GND (power), D8 GND (power), D9 VCC (power), D10 GND (power), D11 VCC (power), D12 GND (power), D13 GND (power), D14 TDO (out), E4 GND (power), E5 NC, E9 CLK3 (in), E13 VCC (power), E15 NC, F4 VCC (power), F13 GND (power), G4 GND (power), G7 VCC (power), G8 GND (power), G9 GND (power), G10 VCC (power), G13 VCC (power), H4 VCC (power), H7 GND (power), H8 VCC (power), H9 VCC (power), H10 GND (power), H13 GND (power), J4 GND (power), J7 GND (power), J8 VCC (power), J9 VCC (power), J10 GND (power), J13 GND (power), K4 VCC (power), K7 VCC (power), K8 GND (power), K9 GND (power), K10 VCC (power), K13 VCC (power), L4 GND (power), L13 GND (power), M4 VCC (power), M13 GND (power), N3 TCK (in), N4 GND (power), N5 GND (power), N6 VCC (power), N7 GND (power), N8 GND (power), N9 VCC (power), N10 GND (power), N11 VCC (power), N12 GND (power), N13 VCC (power), P3 TMS (in), T8 CLK1 (in), T11 CLK2 (in)

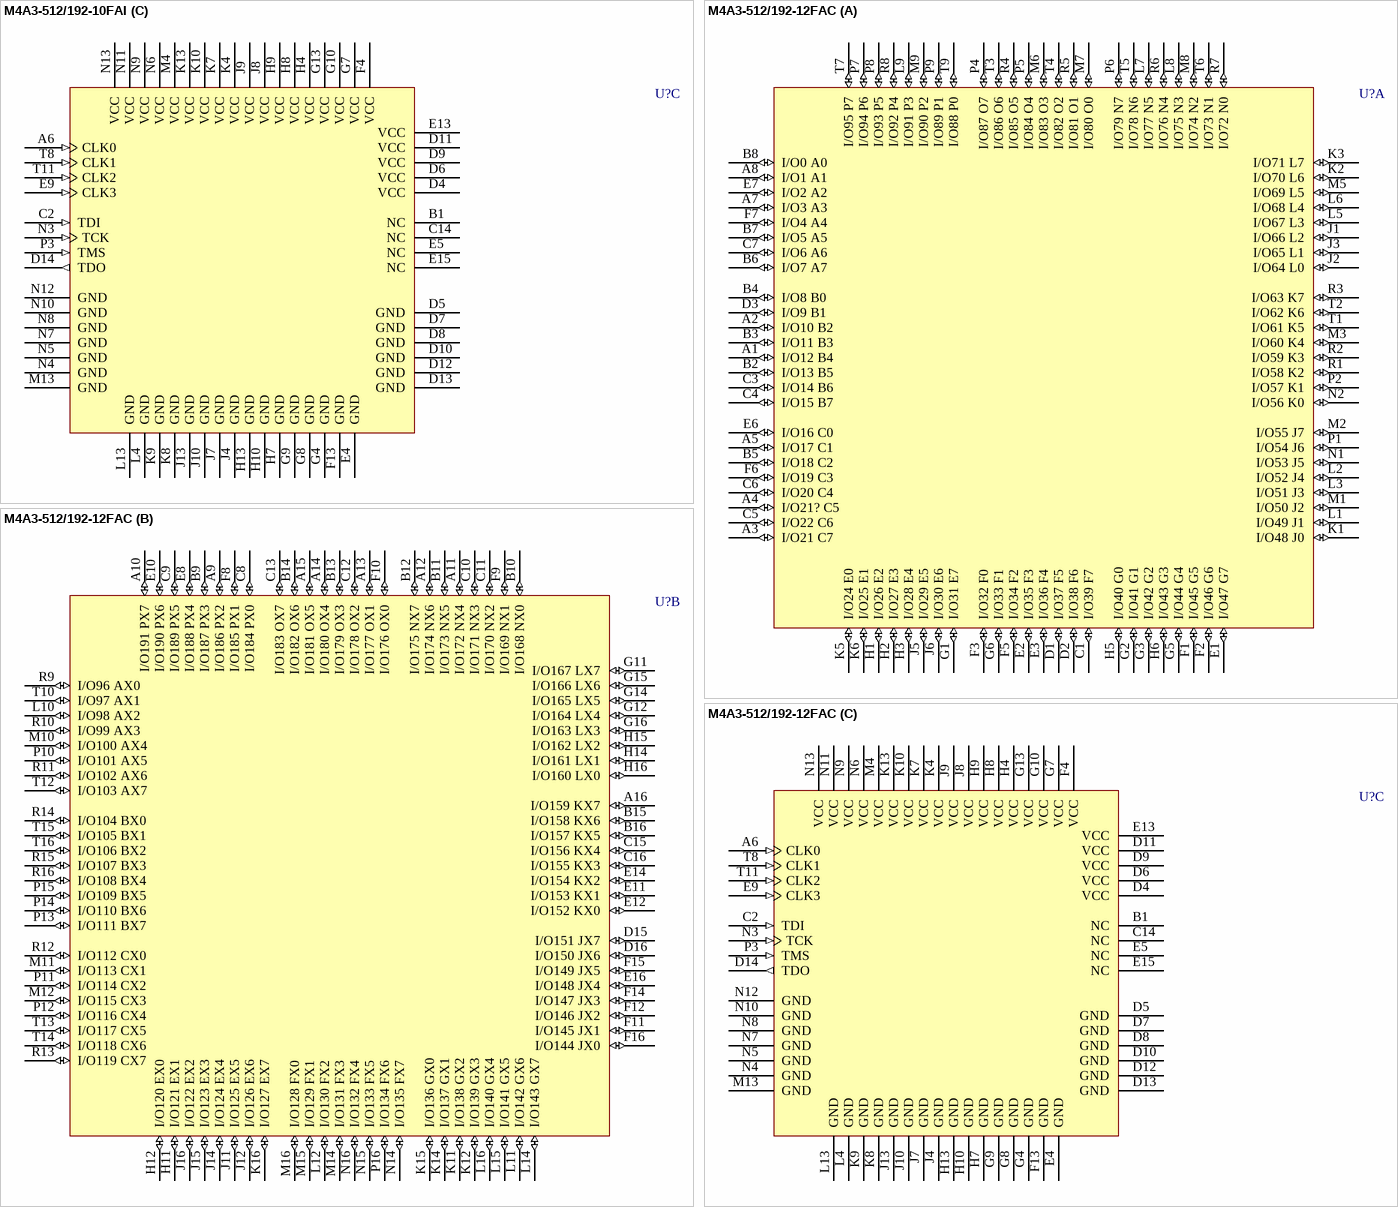
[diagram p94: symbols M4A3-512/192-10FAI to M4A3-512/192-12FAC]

## M4A3-512/192-10FAI
designator U?
High-Performance EE CMOS In-System Programmable Logic
footprint fpBGA256 (BGA, 256-Leads, Body 17x17mm, Pitch 1mm)
3D model M4A3-fpBGA256 (256-Ball Fine Pitch Ball Grid Array (fpBGA256))
part A pins: A1 I/O12 B4 (io), A2 I/O10 B2 (io), A3 I/O21 C7 (io), A4 I/O21? C5 (io), A5 I/O17 C1 (io), A7 I/O3 A3 (io), A8 I/O1 A1 (io), B2 I/O13 B5 (io), B3 I/O11 B3 (io), B4 I/O8 B0 (io), B5 I/O18 C2 (io), B6 I/O7 A7 (io), B7 I/O5 A5 (io), B8 I/O0 A0 (io), C1 I/O39 F7 (io), C3 I/O14 B6 (io), C4 I/O15 B7 (io), C5 I/O22 C6 (io), C6 I/O20 C4 (io), C7 I/O6 A6 (io), D1 I/O37 F5 (io), D2 I/O38 F6 (io), D3 I/O9 B1 (io), E1 I/O47 G7 (io), E2 I/O35 F3 (io), E3 I/O36 F4 (io), E6 I/O16 C0 (io), E7 I/O2 A2 (io), F1 I/O45 G5 (io), F2 I/O46 G6 (io), F3 I/O32 F0 (io), F5 I/O34 F2 (io), F6 I/O19 C3 (io), F7 I/O4 A4 (io), G1 I/O31 E7 (io), G2 I/O41 G1 (io), G3 I/O42 G2 (io), G5 I/O44 G4 (io), G6 I/O33 F1 (io), H1 I/O26 E2 (io), H2 I/O27 E3 (io), H3 I/O28 E4 (io), H5 I/O40 G0 (io), H6 I/O43 G3 (io), J1 I/O66 L2 (io), J2 I/O64 L0 (io), J3 I/O65 L1 (io), J5 I/O29 E5 (io), J6 I/O30 E6 (io), K1 I/O48 J0 (io), K2 I/O70 L6 (io), K3 I/O71 L7 (io), K5 I/O24 E0 (io), K6 I/O25 E1 (io), L1 I/O49 J1 (io), L2 I/O52 J4 (io), L3 I/O51 J3 (io), L5 I/O67 L3 (io), L6 I/O68 L4 (io), L7 I/O77 N5 (io), L8 I/O75 N3 (io), L9 I/O91 P3 (io), M1 I/O50 J2 (io), M2 I/O55 J7 (io), M3 I/O60 K4 (io), M5 I/O69 L5 (io), M6 I/O83 O3 (io), M7 I/O80 O0 (io), M8 I/O74 N2 (io), M9 I/O90 P2 (io), N1 I/O53 J5 (io), N2 I/O56 K0 (io), P1 I/O54 J6 (io), P2 I/O57 K1 (io), P4 I/O87 O7 (io), P5 I/O84 O4 (io), P6 I/O79 N7 (io), P7 I/O94 P6 (io), P8 I/O93 P5 (io), P9 I/O89 P1 (io), R1 I/O58 K2 (io), R2 I/O59 K3 (io), R3 I/O63 K7 (io), R4 I/O85 O5 (io), R5 I/O81 O1 (io), R6 I/O76 N4 (io), R7 I/O72 N0 (io), R8 I/O92 P4 (io), T1 I/O61 K5 (io), T2 I/O62 K6 (io), T3 I/O86 O6 (io), T4 I/O82 O2 (io), T5 I/O78 N6 (io), T6 I/O73 N1 (io), T7 I/O95 P7 (io), T9 I/O88 P0 (io)
part B pins: A9 I/O186 PX2 (io), A10 I/O191 PX7 (io), A11 I/O172 NX4 (io), A12 I/O174 NX6 (io), A13 I/O177 OX1 (io), A14 I/O180 OX4 (io), A15 I/O181 OX5 (io), A16 I/O159 KX7 (io), B9 I/O187 PX3 (io), B10 I/O168 NX0 (io), B11 I/O173 NX5 (io), B12 I/O175 NX7 (io), B13 I/O179 OX3 (io), B14 I/O182 OX6 (io), B15 I/O158 KX6 (io), B16 I/O157 KX5 (io), C8 I/O184 PX0 (io), C9 I/O189 PX5 (io), C10 I/O171 NX3 (io), C11 I/O170 NX2 (io), C12 I/O178 OX2 (io), C13 I/O183 OX7 (io), C15 I/O156 KX4 (io), C16 I/O155 KX3 (io), D15 I/O151 JX7 (io), D16 I/O150 JX6 (io), E8 I/O188 PX4 (io), E10 I/O190 PX6 (io), E11 I/O153 KX1 (io), E12 I/O152 KX0 (io), E14 I/O154 KX2 (io), E16 I/O148 JX4 (io), F8 I/O185 PX1 (io), F9 I/O169 NX1 (io), F10 I/O176 OX0 (io), F11 I/O145 JX1 (io), F12 I/O146 JX2 (io), F14 I/O147 JX3 (io), F15 I/O149 JX5 (io), F16 I/O144 JX0 (io), G11 I/O167 LX7 (io), G12 I/O164 LX4 (io), G14 I/O165 LX5 (io), G15 I/O166 LX6 (io), G16 I/O163 LX3 (io), H11 I/O121 EX1 (io), H12 I/O120 EX0 (io), H14 I/O161 LX1 (io), H15 I/O162 LX2 (io), H16 I/O160 LX0 (io), J11 I/O125 EX5 (io), J12 I/O126 EX6 (io), J14 I/O124 EX4 (io), J15 I/O123 EX3 (io), J16 I/O122 EX2 (io), K11 I/O138 GX2 (io), K12 I/O139 GX3 (io), K14 I/O137 GX1 (io), K15 I/O136 GX0 (io), K16 I/O127 EX7 (io), L10 I/O98 AX2 (io), L11 I/O142 GX6 (io), L12 I/O130 FX2 (io), L14 I/O143 GX7 (io), L15 I/O141 GX5 (io), L16 I/O140 GX4 (io), M10 I/O100 AX4 (io), M11 I/O113 CX1 (io), M12 I/O115 CX3 (io), M14 I/O131 FX3 (io), M15 I/O129 FX1 (io), M16 I/O128 FX0 (io), N14 I/O135 FX7 (io), N15 I/O133 FX5 (io), N16 I/O132 FX4 (io), P10 I/O101 AX5 (io), P11 I/O114 CX2 (io), P12 I/O116 CX4 (io), P13 I/O111 BX7 (io), P14 I/O110 BX6 (io), P15 I/O109 BX5 (io), P16 I/O134 FX6 (io), R9 I/O96 AX0 (io), R10 I/O99 AX3 (io), R11 I/O102 AX6 (io), R12 I/O112 CX0 (io), R13 I/O119 CX7 (io), R14 I/O104 BX0 (io), R15 I/O107 BX3 (io), R16 I/O108 BX4 (io), T10 I/O97 AX1 (io), T12 I/O103 AX7 (io), T13 I/O117 CX5 (io), T14 I/O118 CX6 (io), T15 I/O105 BX1 (io), T16 I/O106 BX2 (io)
part C pins: A6 CLK0 (in), B1 NC, C2 TDI (in), C14 NC, D4 VCC (power), D5 GND (power), D6 VCC (power), D7 GND (power), D8 GND (power), D9 VCC (power), D10 GND (power), D11 VCC (power), D12 GND (power), D13 GND (power), D14 TDO (out), E4 GND (power), E5 NC, E9 CLK3 (in), E13 VCC (power), E15 NC, F4 VCC (power), F13 GND (power), G4 GND (power), G7 VCC (power), G8 GND (power), G9 GND (power), G10 VCC (power), G13 VCC (power), H4 VCC (power), H7 GND (power), H8 VCC (power), H9 VCC (power), H10 GND (power), H13 GND (power), J4 GND (power), J7 GND (power), J8 VCC (power), J9 VCC (power), J10 GND (power), J13 GND (power), K4 VCC (power), K7 VCC (power), K8 GND (power), K9 GND (power), K10 VCC (power), K13 VCC (power), L4 GND (power), L13 GND (power), M4 VCC (power), M13 GND (power), N3 TCK (in), N4 GND (power), N5 GND (power), N6 VCC (power), N7 GND (power), N8 GND (power), N9 VCC (power), N10 GND (power), N11 VCC (power), N12 GND (power), N13 VCC (power), P3 TMS (in), T8 CLK1 (in), T11 CLK2 (in)

## M4A3-512/192-12FAC
designator U?
High-Performance EE CMOS In-System Programmable Logic
footprint fpBGA256 (BGA, 256-Leads, Body 17x17mm, Pitch 1mm)
3D model M4A3-fpBGA256 (256-Ball Fine Pitch Ball Grid Array (fpBGA256))
part A pins: A1 I/O12 B4 (io), A2 I/O10 B2 (io), A3 I/O21 C7 (io), A4 I/O21? C5 (io), A5 I/O17 C1 (io), A7 I/O3 A3 (io), A8 I/O1 A1 (io), B2 I/O13 B5 (io), B3 I/O11 B3 (io), B4 I/O8 B0 (io), B5 I/O18 C2 (io), B6 I/O7 A7 (io), B7 I/O5 A5 (io), B8 I/O0 A0 (io), C1 I/O39 F7 (io), C3 I/O14 B6 (io), C4 I/O15 B7 (io), C5 I/O22 C6 (io), C6 I/O20 C4 (io), C7 I/O6 A6 (io), D1 I/O37 F5 (io), D2 I/O38 F6 (io), D3 I/O9 B1 (io), E1 I/O47 G7 (io), E2 I/O35 F3 (io), E3 I/O36 F4 (io), E6 I/O16 C0 (io), E7 I/O2 A2 (io), F1 I/O45 G5 (io), F2 I/O46 G6 (io), F3 I/O32 F0 (io), F5 I/O34 F2 (io), F6 I/O19 C3 (io), F7 I/O4 A4 (io), G1 I/O31 E7 (io), G2 I/O41 G1 (io), G3 I/O42 G2 (io), G5 I/O44 G4 (io), G6 I/O33 F1 (io), H1 I/O26 E2 (io), H2 I/O27 E3 (io), H3 I/O28 E4 (io), H5 I/O40 G0 (io), H6 I/O43 G3 (io), J1 I/O66 L2 (io), J2 I/O64 L0 (io), J3 I/O65 L1 (io), J5 I/O29 E5 (io), J6 I/O30 E6 (io), K1 I/O48 J0 (io), K2 I/O70 L6 (io), K3 I/O71 L7 (io), K5 I/O24 E0 (io), K6 I/O25 E1 (io), L1 I/O49 J1 (io), L2 I/O52 J4 (io), L3 I/O51 J3 (io), L5 I/O67 L3 (io), L6 I/O68 L4 (io), L7 I/O77 N5 (io), L8 I/O75 N3 (io), L9 I/O91 P3 (io), M1 I/O50 J2 (io), M2 I/O55 J7 (io), M3 I/O60 K4 (io), M5 I/O69 L5 (io), M6 I/O83 O3 (io), M7 I/O80 O0 (io), M8 I/O74 N2 (io), M9 I/O90 P2 (io), N1 I/O53 J5 (io), N2 I/O56 K0 (io), P1 I/O54 J6 (io), P2 I/O57 K1 (io), P4 I/O87 O7 (io), P5 I/O84 O4 (io), P6 I/O79 N7 (io), P7 I/O94 P6 (io), P8 I/O93 P5 (io), P9 I/O89 P1 (io), R1 I/O58 K2 (io), R2 I/O59 K3 (io), R3 I/O63 K7 (io), R4 I/O85 O5 (io), R5 I/O81 O1 (io), R6 I/O76 N4 (io), R7 I/O72 N0 (io), R8 I/O92 P4 (io), T1 I/O61 K5 (io), T2 I/O62 K6 (io), T3 I/O86 O6 (io), T4 I/O82 O2 (io), T5 I/O78 N6 (io), T6 I/O73 N1 (io), T7 I/O95 P7 (io), T9 I/O88 P0 (io)
part B pins: A9 I/O186 PX2 (io), A10 I/O191 PX7 (io), A11 I/O172 NX4 (io), A12 I/O174 NX6 (io), A13 I/O177 OX1 (io), A14 I/O180 OX4 (io), A15 I/O181 OX5 (io), A16 I/O159 KX7 (io), B9 I/O187 PX3 (io), B10 I/O168 NX0 (io), B11 I/O173 NX5 (io), B12 I/O175 NX7 (io), B13 I/O179 OX3 (io), B14 I/O182 OX6 (io), B15 I/O158 KX6 (io), B16 I/O157 KX5 (io), C8 I/O184 PX0 (io), C9 I/O189 PX5 (io), C10 I/O171 NX3 (io), C11 I/O170 NX2 (io), C12 I/O178 OX2 (io), C13 I/O183 OX7 (io), C15 I/O156 KX4 (io), C16 I/O155 KX3 (io), D15 I/O151 JX7 (io), D16 I/O150 JX6 (io), E8 I/O188 PX4 (io), E10 I/O190 PX6 (io), E11 I/O153 KX1 (io), E12 I/O152 KX0 (io), E14 I/O154 KX2 (io), E16 I/O148 JX4 (io), F8 I/O185 PX1 (io), F9 I/O169 NX1 (io), F10 I/O176 OX0 (io), F11 I/O145 JX1 (io), F12 I/O146 JX2 (io), F14 I/O147 JX3 (io), F15 I/O149 JX5 (io), F16 I/O144 JX0 (io), G11 I/O167 LX7 (io), G12 I/O164 LX4 (io), G14 I/O165 LX5 (io), G15 I/O166 LX6 (io), G16 I/O163 LX3 (io), H11 I/O121 EX1 (io), H12 I/O120 EX0 (io), H14 I/O161 LX1 (io), H15 I/O162 LX2 (io), H16 I/O160 LX0 (io), J11 I/O125 EX5 (io), J12 I/O126 EX6 (io), J14 I/O124 EX4 (io), J15 I/O123 EX3 (io), J16 I/O122 EX2 (io), K11 I/O138 GX2 (io), K12 I/O139 GX3 (io), K14 I/O137 GX1 (io), K15 I/O136 GX0 (io), K16 I/O127 EX7 (io), L10 I/O98 AX2 (io), L11 I/O142 GX6 (io), L12 I/O130 FX2 (io), L14 I/O143 GX7 (io), L15 I/O141 GX5 (io), L16 I/O140 GX4 (io), M10 I/O100 AX4 (io), M11 I/O113 CX1 (io), M12 I/O115 CX3 (io), M14 I/O131 FX3 (io), M15 I/O129 FX1 (io), M16 I/O128 FX0 (io), N14 I/O135 FX7 (io), N15 I/O133 FX5 (io), N16 I/O132 FX4 (io), P10 I/O101 AX5 (io), P11 I/O114 CX2 (io), P12 I/O116 CX4 (io), P13 I/O111 BX7 (io), P14 I/O110 BX6 (io), P15 I/O109 BX5 (io), P16 I/O134 FX6 (io), R9 I/O96 AX0 (io), R10 I/O99 AX3 (io), R11 I/O102 AX6 (io), R12 I/O112 CX0 (io), R13 I/O119 CX7 (io), R14 I/O104 BX0 (io), R15 I/O107 BX3 (io), R16 I/O108 BX4 (io), T10 I/O97 AX1 (io), T12 I/O103 AX7 (io), T13 I/O117 CX5 (io), T14 I/O118 CX6 (io), T15 I/O105 BX1 (io), T16 I/O106 BX2 (io)
part C pins: A6 CLK0 (in), B1 NC, C2 TDI (in), C14 NC, D4 VCC (power), D5 GND (power), D6 VCC (power), D7 GND (power), D8 GND (power), D9 VCC (power), D10 GND (power), D11 VCC (power), D12 GND (power), D13 GND (power), D14 TDO (out), E4 GND (power), E5 NC, E9 CLK3 (in), E13 VCC (power), E15 NC, F4 VCC (power), F13 GND (power), G4 GND (power), G7 VCC (power), G8 GND (power), G9 GND (power), G10 VCC (power), G13 VCC (power), H4 VCC (power), H7 GND (power), H8 VCC (power), H9 VCC (power), H10 GND (power), H13 GND (power), J4 GND (power), J7 GND (power), J8 VCC (power), J9 VCC (power), J10 GND (power), J13 GND (power), K4 VCC (power), K7 VCC (power), K8 GND (power), K9 GND (power), K10 VCC (power), K13 VCC (power), L4 GND (power), L13 GND (power), M4 VCC (power), M13 GND (power), N3 TCK (in), N4 GND (power), N5 GND (power), N6 VCC (power), N7 GND (power), N8 GND (power), N9 VCC (power), N10 GND (power), N11 VCC (power), N12 GND (power), N13 VCC (power), P3 TMS (in), T8 CLK1 (in), T11 CLK2 (in)

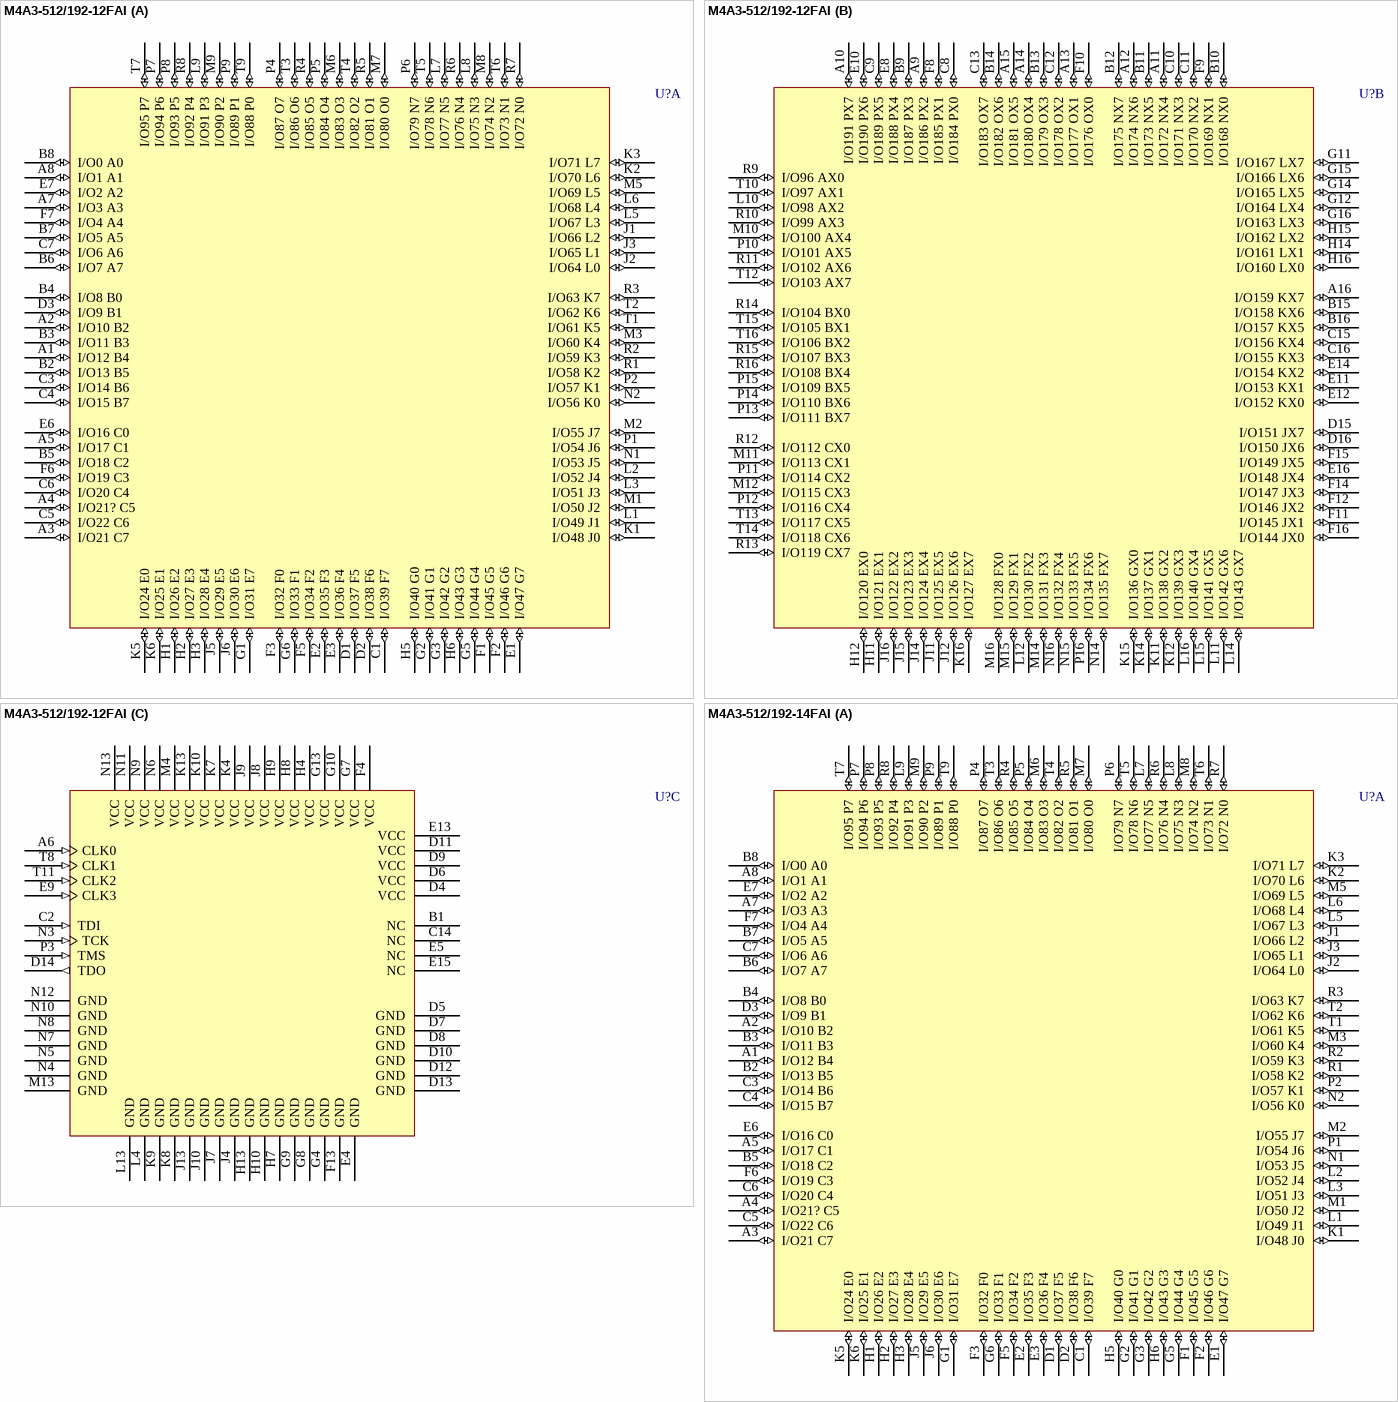
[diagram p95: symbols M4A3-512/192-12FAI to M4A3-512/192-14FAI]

## M4A3-512/192-12FAI
designator U?
High-Performance EE CMOS In-System Programmable Logic
footprint fpBGA256 (BGA, 256-Leads, Body 17x17mm, Pitch 1mm)
3D model M4A3-fpBGA256 (256-Ball Fine Pitch Ball Grid Array (fpBGA256))
part A pins: A1 I/O12 B4 (io), A2 I/O10 B2 (io), A3 I/O21 C7 (io), A4 I/O21? C5 (io), A5 I/O17 C1 (io), A7 I/O3 A3 (io), A8 I/O1 A1 (io), B2 I/O13 B5 (io), B3 I/O11 B3 (io), B4 I/O8 B0 (io), B5 I/O18 C2 (io), B6 I/O7 A7 (io), B7 I/O5 A5 (io), B8 I/O0 A0 (io), C1 I/O39 F7 (io), C3 I/O14 B6 (io), C4 I/O15 B7 (io), C5 I/O22 C6 (io), C6 I/O20 C4 (io), C7 I/O6 A6 (io), D1 I/O37 F5 (io), D2 I/O38 F6 (io), D3 I/O9 B1 (io), E1 I/O47 G7 (io), E2 I/O35 F3 (io), E3 I/O36 F4 (io), E6 I/O16 C0 (io), E7 I/O2 A2 (io), F1 I/O45 G5 (io), F2 I/O46 G6 (io), F3 I/O32 F0 (io), F5 I/O34 F2 (io), F6 I/O19 C3 (io), F7 I/O4 A4 (io), G1 I/O31 E7 (io), G2 I/O41 G1 (io), G3 I/O42 G2 (io), G5 I/O44 G4 (io), G6 I/O33 F1 (io), H1 I/O26 E2 (io), H2 I/O27 E3 (io), H3 I/O28 E4 (io), H5 I/O40 G0 (io), H6 I/O43 G3 (io), J1 I/O66 L2 (io), J2 I/O64 L0 (io), J3 I/O65 L1 (io), J5 I/O29 E5 (io), J6 I/O30 E6 (io), K1 I/O48 J0 (io), K2 I/O70 L6 (io), K3 I/O71 L7 (io), K5 I/O24 E0 (io), K6 I/O25 E1 (io), L1 I/O49 J1 (io), L2 I/O52 J4 (io), L3 I/O51 J3 (io), L5 I/O67 L3 (io), L6 I/O68 L4 (io), L7 I/O77 N5 (io), L8 I/O75 N3 (io), L9 I/O91 P3 (io), M1 I/O50 J2 (io), M2 I/O55 J7 (io), M3 I/O60 K4 (io), M5 I/O69 L5 (io), M6 I/O83 O3 (io), M7 I/O80 O0 (io), M8 I/O74 N2 (io), M9 I/O90 P2 (io), N1 I/O53 J5 (io), N2 I/O56 K0 (io), P1 I/O54 J6 (io), P2 I/O57 K1 (io), P4 I/O87 O7 (io), P5 I/O84 O4 (io), P6 I/O79 N7 (io), P7 I/O94 P6 (io), P8 I/O93 P5 (io), P9 I/O89 P1 (io), R1 I/O58 K2 (io), R2 I/O59 K3 (io), R3 I/O63 K7 (io), R4 I/O85 O5 (io), R5 I/O81 O1 (io), R6 I/O76 N4 (io), R7 I/O72 N0 (io), R8 I/O92 P4 (io), T1 I/O61 K5 (io), T2 I/O62 K6 (io), T3 I/O86 O6 (io), T4 I/O82 O2 (io), T5 I/O78 N6 (io), T6 I/O73 N1 (io), T7 I/O95 P7 (io), T9 I/O88 P0 (io)
part B pins: A9 I/O186 PX2 (io), A10 I/O191 PX7 (io), A11 I/O172 NX4 (io), A12 I/O174 NX6 (io), A13 I/O177 OX1 (io), A14 I/O180 OX4 (io), A15 I/O181 OX5 (io), A16 I/O159 KX7 (io), B9 I/O187 PX3 (io), B10 I/O168 NX0 (io), B11 I/O173 NX5 (io), B12 I/O175 NX7 (io), B13 I/O179 OX3 (io), B14 I/O182 OX6 (io), B15 I/O158 KX6 (io), B16 I/O157 KX5 (io), C8 I/O184 PX0 (io), C9 I/O189 PX5 (io), C10 I/O171 NX3 (io), C11 I/O170 NX2 (io), C12 I/O178 OX2 (io), C13 I/O183 OX7 (io), C15 I/O156 KX4 (io), C16 I/O155 KX3 (io), D15 I/O151 JX7 (io), D16 I/O150 JX6 (io), E8 I/O188 PX4 (io), E10 I/O190 PX6 (io), E11 I/O153 KX1 (io), E12 I/O152 KX0 (io), E14 I/O154 KX2 (io), E16 I/O148 JX4 (io), F8 I/O185 PX1 (io), F9 I/O169 NX1 (io), F10 I/O176 OX0 (io), F11 I/O145 JX1 (io), F12 I/O146 JX2 (io), F14 I/O147 JX3 (io), F15 I/O149 JX5 (io), F16 I/O144 JX0 (io), G11 I/O167 LX7 (io), G12 I/O164 LX4 (io), G14 I/O165 LX5 (io), G15 I/O166 LX6 (io), G16 I/O163 LX3 (io), H11 I/O121 EX1 (io), H12 I/O120 EX0 (io), H14 I/O161 LX1 (io), H15 I/O162 LX2 (io), H16 I/O160 LX0 (io), J11 I/O125 EX5 (io), J12 I/O126 EX6 (io), J14 I/O124 EX4 (io), J15 I/O123 EX3 (io), J16 I/O122 EX2 (io), K11 I/O138 GX2 (io), K12 I/O139 GX3 (io), K14 I/O137 GX1 (io), K15 I/O136 GX0 (io), K16 I/O127 EX7 (io), L10 I/O98 AX2 (io), L11 I/O142 GX6 (io), L12 I/O130 FX2 (io), L14 I/O143 GX7 (io), L15 I/O141 GX5 (io), L16 I/O140 GX4 (io), M10 I/O100 AX4 (io), M11 I/O113 CX1 (io), M12 I/O115 CX3 (io), M14 I/O131 FX3 (io), M15 I/O129 FX1 (io), M16 I/O128 FX0 (io), N14 I/O135 FX7 (io), N15 I/O133 FX5 (io), N16 I/O132 FX4 (io), P10 I/O101 AX5 (io), P11 I/O114 CX2 (io), P12 I/O116 CX4 (io), P13 I/O111 BX7 (io), P14 I/O110 BX6 (io), P15 I/O109 BX5 (io), P16 I/O134 FX6 (io), R9 I/O96 AX0 (io), R10 I/O99 AX3 (io), R11 I/O102 AX6 (io), R12 I/O112 CX0 (io), R13 I/O119 CX7 (io), R14 I/O104 BX0 (io), R15 I/O107 BX3 (io), R16 I/O108 BX4 (io), T10 I/O97 AX1 (io), T12 I/O103 AX7 (io), T13 I/O117 CX5 (io), T14 I/O118 CX6 (io), T15 I/O105 BX1 (io), T16 I/O106 BX2 (io)
part C pins: A6 CLK0 (in), B1 NC, C2 TDI (in), C14 NC, D4 VCC (power), D5 GND (power), D6 VCC (power), D7 GND (power), D8 GND (power), D9 VCC (power), D10 GND (power), D11 VCC (power), D12 GND (power), D13 GND (power), D14 TDO (out), E4 GND (power), E5 NC, E9 CLK3 (in), E13 VCC (power), E15 NC, F4 VCC (power), F13 GND (power), G4 GND (power), G7 VCC (power), G8 GND (power), G9 GND (power), G10 VCC (power), G13 VCC (power), H4 VCC (power), H7 GND (power), H8 VCC (power), H9 VCC (power), H10 GND (power), H13 GND (power), J4 GND (power), J7 GND (power), J8 VCC (power), J9 VCC (power), J10 GND (power), J13 GND (power), K4 VCC (power), K7 VCC (power), K8 GND (power), K9 GND (power), K10 VCC (power), K13 VCC (power), L4 GND (power), L13 GND (power), M4 VCC (power), M13 GND (power), N3 TCK (in), N4 GND (power), N5 GND (power), N6 VCC (power), N7 GND (power), N8 GND (power), N9 VCC (power), N10 GND (power), N11 VCC (power), N12 GND (power), N13 VCC (power), P3 TMS (in), T8 CLK1 (in), T11 CLK2 (in)

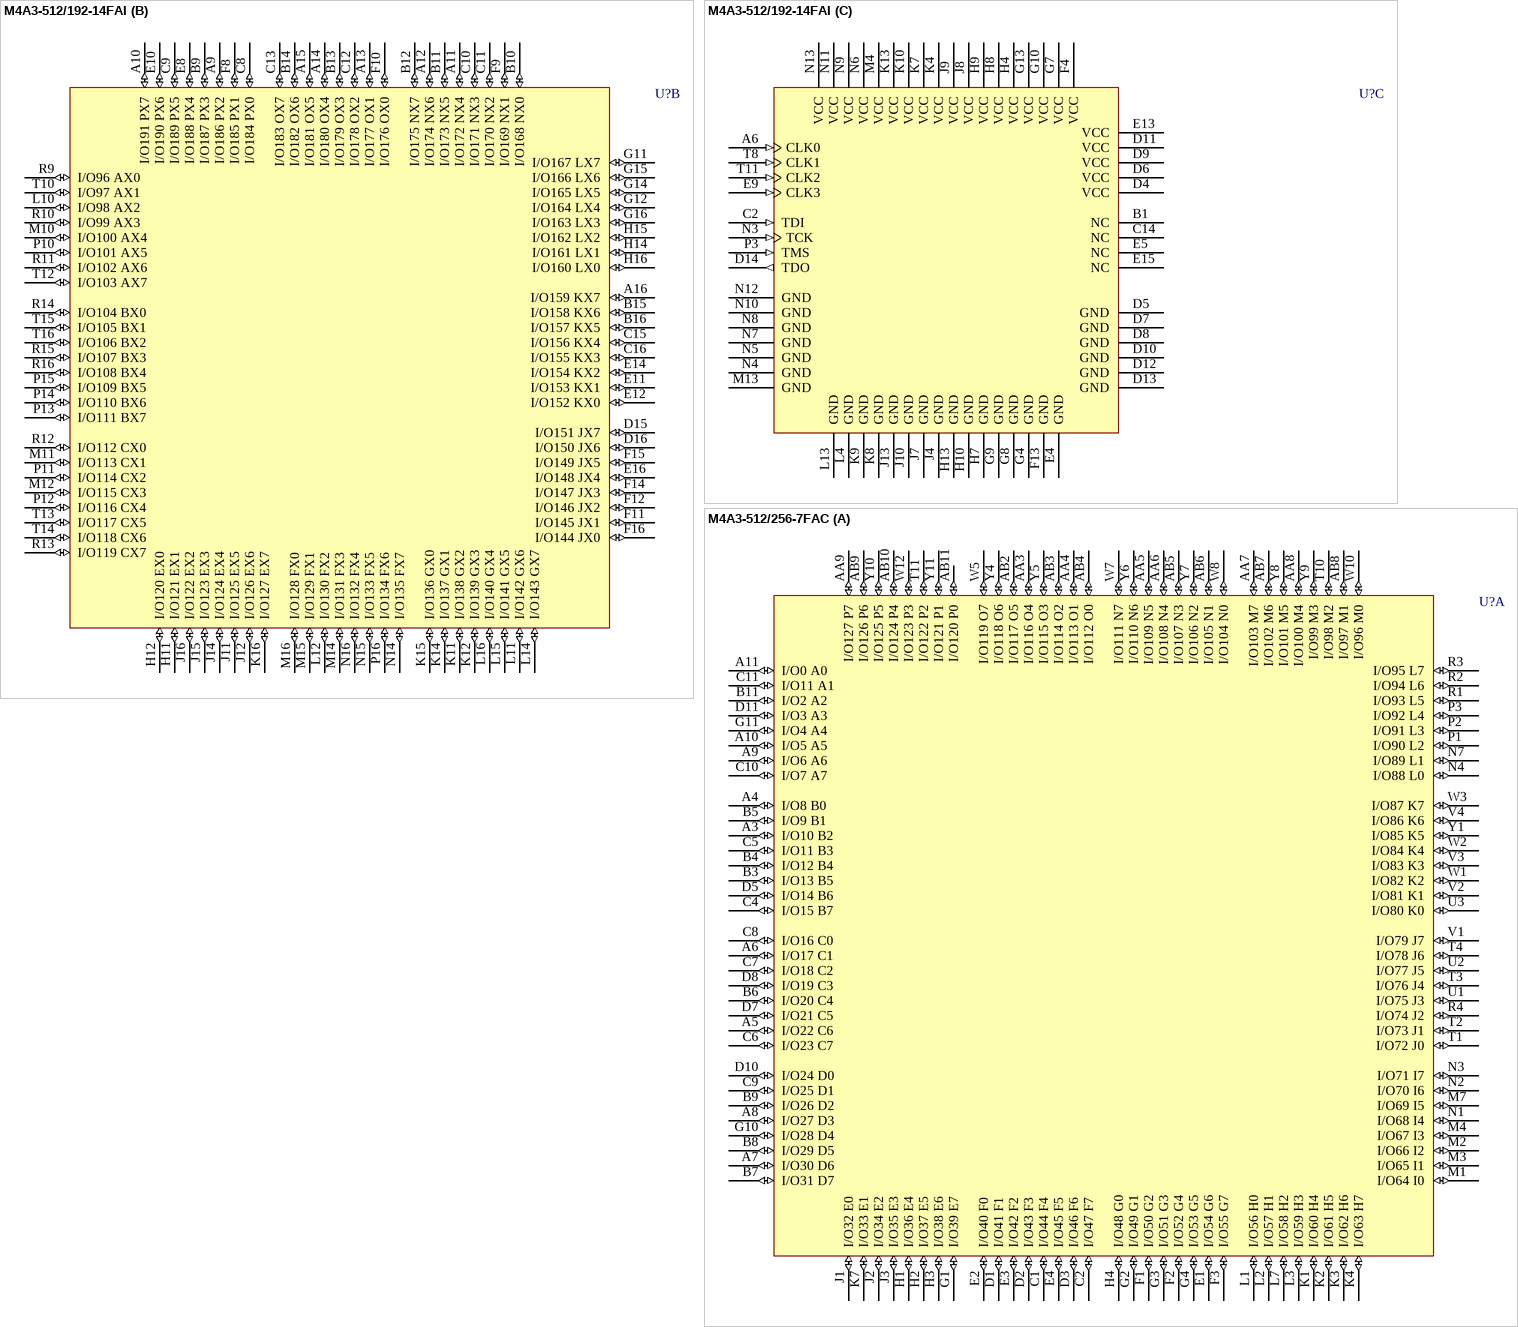
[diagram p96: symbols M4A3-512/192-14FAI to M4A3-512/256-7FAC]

## M4A3-512/192-14FAI
designator U?
High-Performance EE CMOS In-System Programmable Logic
footprint fpBGA256 (BGA, 256-Leads, Body 17x17mm, Pitch 1mm)
3D model M4A3-fpBGA256 (256-Ball Fine Pitch Ball Grid Array (fpBGA256))
part A pins: A1 I/O12 B4 (io), A2 I/O10 B2 (io), A3 I/O21 C7 (io), A4 I/O21? C5 (io), A5 I/O17 C1 (io), A7 I/O3 A3 (io), A8 I/O1 A1 (io), B2 I/O13 B5 (io), B3 I/O11 B3 (io), B4 I/O8 B0 (io), B5 I/O18 C2 (io), B6 I/O7 A7 (io), B7 I/O5 A5 (io), B8 I/O0 A0 (io), C1 I/O39 F7 (io), C3 I/O14 B6 (io), C4 I/O15 B7 (io), C5 I/O22 C6 (io), C6 I/O20 C4 (io), C7 I/O6 A6 (io), D1 I/O37 F5 (io), D2 I/O38 F6 (io), D3 I/O9 B1 (io), E1 I/O47 G7 (io), E2 I/O35 F3 (io), E3 I/O36 F4 (io), E6 I/O16 C0 (io), E7 I/O2 A2 (io), F1 I/O45 G5 (io), F2 I/O46 G6 (io), F3 I/O32 F0 (io), F5 I/O34 F2 (io), F6 I/O19 C3 (io), F7 I/O4 A4 (io), G1 I/O31 E7 (io), G2 I/O41 G1 (io), G3 I/O42 G2 (io), G5 I/O44 G4 (io), G6 I/O33 F1 (io), H1 I/O26 E2 (io), H2 I/O27 E3 (io), H3 I/O28 E4 (io), H5 I/O40 G0 (io), H6 I/O43 G3 (io), J1 I/O66 L2 (io), J2 I/O64 L0 (io), J3 I/O65 L1 (io), J5 I/O29 E5 (io), J6 I/O30 E6 (io), K1 I/O48 J0 (io), K2 I/O70 L6 (io), K3 I/O71 L7 (io), K5 I/O24 E0 (io), K6 I/O25 E1 (io), L1 I/O49 J1 (io), L2 I/O52 J4 (io), L3 I/O51 J3 (io), L5 I/O67 L3 (io), L6 I/O68 L4 (io), L7 I/O77 N5 (io), L8 I/O75 N3 (io), L9 I/O91 P3 (io), M1 I/O50 J2 (io), M2 I/O55 J7 (io), M3 I/O60 K4 (io), M5 I/O69 L5 (io), M6 I/O83 O3 (io), M7 I/O80 O0 (io), M8 I/O74 N2 (io), M9 I/O90 P2 (io), N1 I/O53 J5 (io), N2 I/O56 K0 (io), P1 I/O54 J6 (io), P2 I/O57 K1 (io), P4 I/O87 O7 (io), P5 I/O84 O4 (io), P6 I/O79 N7 (io), P7 I/O94 P6 (io), P8 I/O93 P5 (io), P9 I/O89 P1 (io), R1 I/O58 K2 (io), R2 I/O59 K3 (io), R3 I/O63 K7 (io), R4 I/O85 O5 (io), R5 I/O81 O1 (io), R6 I/O76 N4 (io), R7 I/O72 N0 (io), R8 I/O92 P4 (io), T1 I/O61 K5 (io), T2 I/O62 K6 (io), T3 I/O86 O6 (io), T4 I/O82 O2 (io), T5 I/O78 N6 (io), T6 I/O73 N1 (io), T7 I/O95 P7 (io), T9 I/O88 P0 (io)
part B pins: A9 I/O186 PX2 (io), A10 I/O191 PX7 (io), A11 I/O172 NX4 (io), A12 I/O174 NX6 (io), A13 I/O177 OX1 (io), A14 I/O180 OX4 (io), A15 I/O181 OX5 (io), A16 I/O159 KX7 (io), B9 I/O187 PX3 (io), B10 I/O168 NX0 (io), B11 I/O173 NX5 (io), B12 I/O175 NX7 (io), B13 I/O179 OX3 (io), B14 I/O182 OX6 (io), B15 I/O158 KX6 (io), B16 I/O157 KX5 (io), C8 I/O184 PX0 (io), C9 I/O189 PX5 (io), C10 I/O171 NX3 (io), C11 I/O170 NX2 (io), C12 I/O178 OX2 (io), C13 I/O183 OX7 (io), C15 I/O156 KX4 (io), C16 I/O155 KX3 (io), D15 I/O151 JX7 (io), D16 I/O150 JX6 (io), E8 I/O188 PX4 (io), E10 I/O190 PX6 (io), E11 I/O153 KX1 (io), E12 I/O152 KX0 (io), E14 I/O154 KX2 (io), E16 I/O148 JX4 (io), F8 I/O185 PX1 (io), F9 I/O169 NX1 (io), F10 I/O176 OX0 (io), F11 I/O145 JX1 (io), F12 I/O146 JX2 (io), F14 I/O147 JX3 (io), F15 I/O149 JX5 (io), F16 I/O144 JX0 (io), G11 I/O167 LX7 (io), G12 I/O164 LX4 (io), G14 I/O165 LX5 (io), G15 I/O166 LX6 (io), G16 I/O163 LX3 (io), H11 I/O121 EX1 (io), H12 I/O120 EX0 (io), H14 I/O161 LX1 (io), H15 I/O162 LX2 (io), H16 I/O160 LX0 (io), J11 I/O125 EX5 (io), J12 I/O126 EX6 (io), J14 I/O124 EX4 (io), J15 I/O123 EX3 (io), J16 I/O122 EX2 (io), K11 I/O138 GX2 (io), K12 I/O139 GX3 (io), K14 I/O137 GX1 (io), K15 I/O136 GX0 (io), K16 I/O127 EX7 (io), L10 I/O98 AX2 (io), L11 I/O142 GX6 (io), L12 I/O130 FX2 (io), L14 I/O143 GX7 (io), L15 I/O141 GX5 (io), L16 I/O140 GX4 (io), M10 I/O100 AX4 (io), M11 I/O113 CX1 (io), M12 I/O115 CX3 (io), M14 I/O131 FX3 (io), M15 I/O129 FX1 (io), M16 I/O128 FX0 (io), N14 I/O135 FX7 (io), N15 I/O133 FX5 (io), N16 I/O132 FX4 (io), P10 I/O101 AX5 (io), P11 I/O114 CX2 (io), P12 I/O116 CX4 (io), P13 I/O111 BX7 (io), P14 I/O110 BX6 (io), P15 I/O109 BX5 (io), P16 I/O134 FX6 (io), R9 I/O96 AX0 (io), R10 I/O99 AX3 (io), R11 I/O102 AX6 (io), R12 I/O112 CX0 (io), R13 I/O119 CX7 (io), R14 I/O104 BX0 (io), R15 I/O107 BX3 (io), R16 I/O108 BX4 (io), T10 I/O97 AX1 (io), T12 I/O103 AX7 (io), T13 I/O117 CX5 (io), T14 I/O118 CX6 (io), T15 I/O105 BX1 (io), T16 I/O106 BX2 (io)
part C pins: A6 CLK0 (in), B1 NC, C2 TDI (in), C14 NC, D4 VCC (power), D5 GND (power), D6 VCC (power), D7 GND (power), D8 GND (power), D9 VCC (power), D10 GND (power), D11 VCC (power), D12 GND (power), D13 GND (power), D14 TDO (out), E4 GND (power), E5 NC, E9 CLK3 (in), E13 VCC (power), E15 NC, F4 VCC (power), F13 GND (power), G4 GND (power), G7 VCC (power), G8 GND (power), G9 GND (power), G10 VCC (power), G13 VCC (power), H4 VCC (power), H7 GND (power), H8 VCC (power), H9 VCC (power), H10 GND (power), H13 GND (power), J4 GND (power), J7 GND (power), J8 VCC (power), J9 VCC (power), J10 GND (power), J13 GND (power), K4 VCC (power), K7 VCC (power), K8 GND (power), K9 GND (power), K10 VCC (power), K13 VCC (power), L4 GND (power), L13 GND (power), M4 VCC (power), M13 GND (power), N3 TCK (in), N4 GND (power), N5 GND (power), N6 VCC (power), N7 GND (power), N8 GND (power), N9 VCC (power), N10 GND (power), N11 VCC (power), N12 GND (power), N13 VCC (power), P3 TMS (in), T8 CLK1 (in), T11 CLK2 (in)

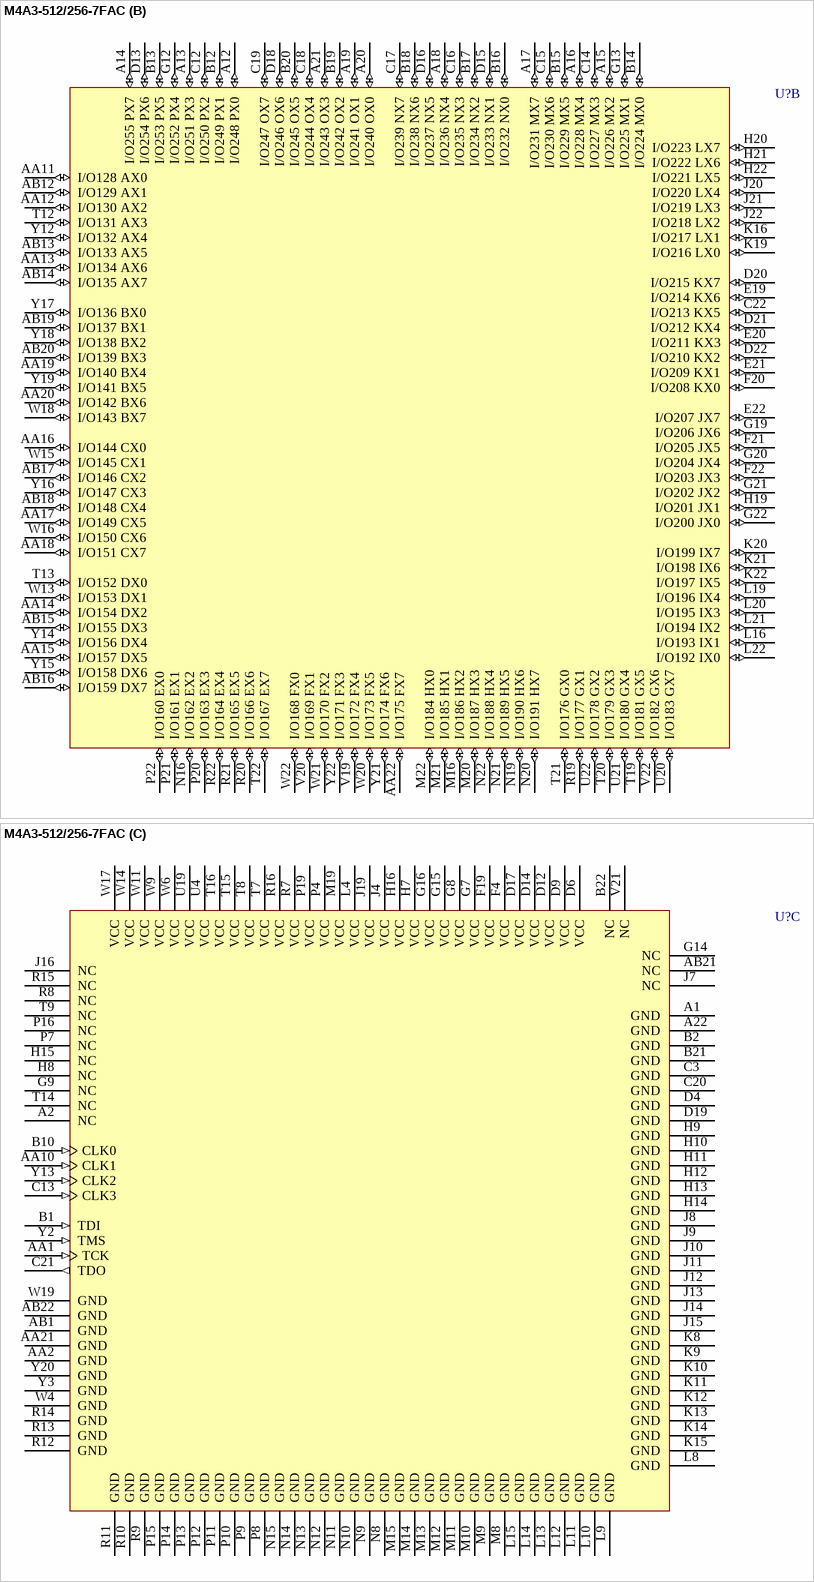
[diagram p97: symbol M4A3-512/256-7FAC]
